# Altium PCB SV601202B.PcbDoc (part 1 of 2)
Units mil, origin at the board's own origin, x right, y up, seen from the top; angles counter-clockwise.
Board outline 3713 x 4037 mil, 6 copper layers (Top Layer, Signal Layer 1, Signal Layer 2, Signal Layer 3, Signal Layer 4, Bottom Layer), stack 60.36 mil thick; 230 components, 115 nets, 621 pads, 197 vias.
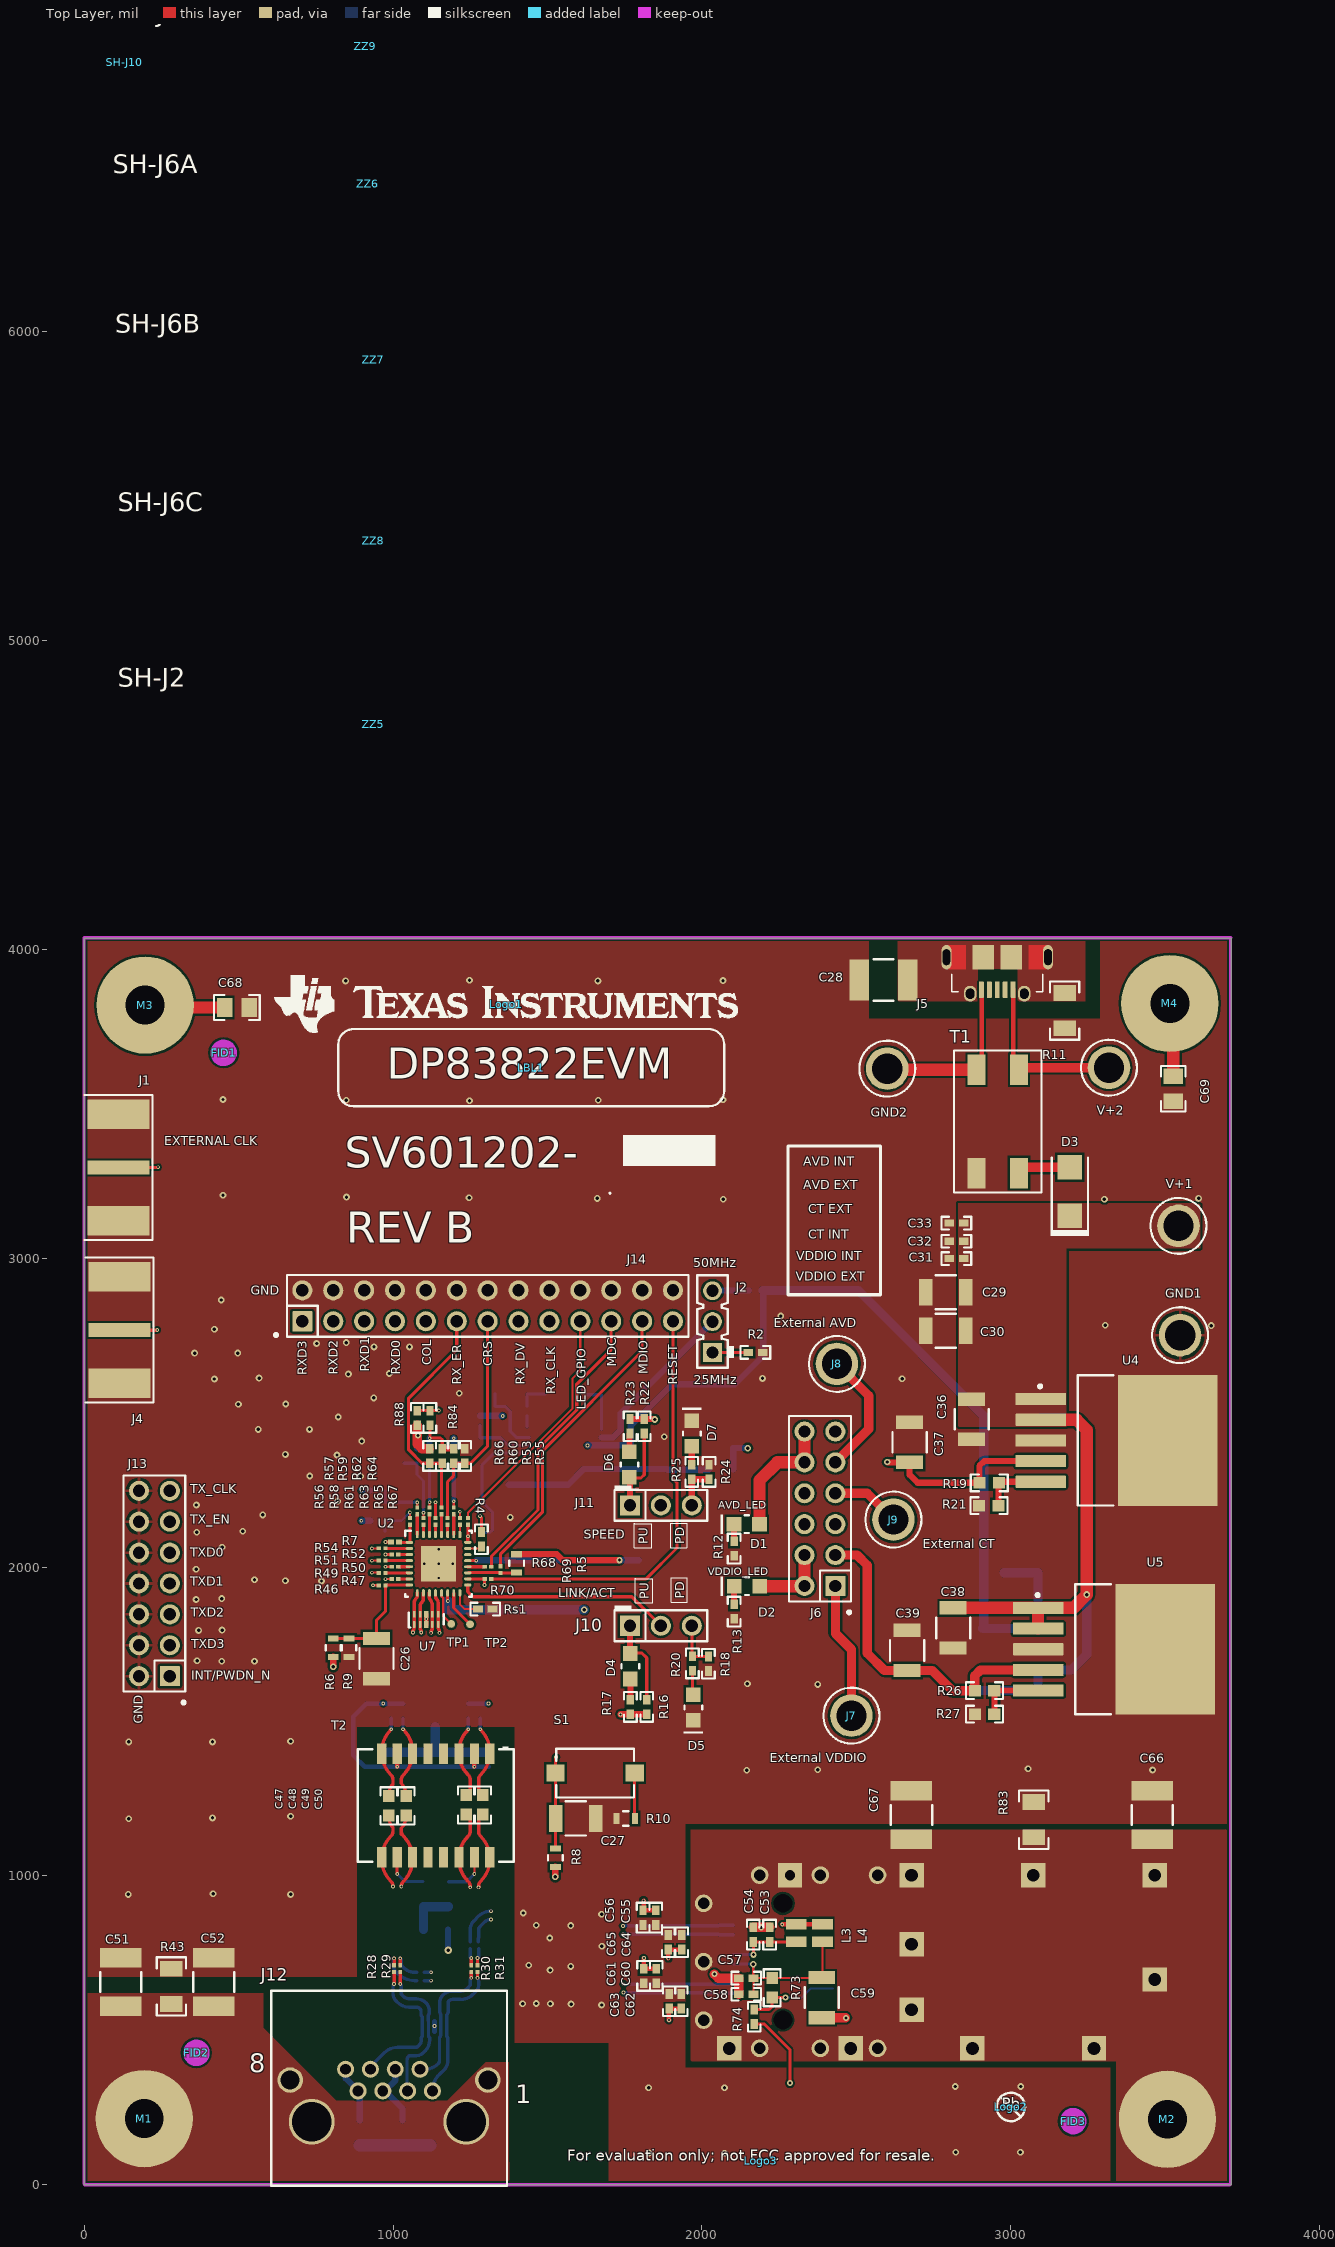
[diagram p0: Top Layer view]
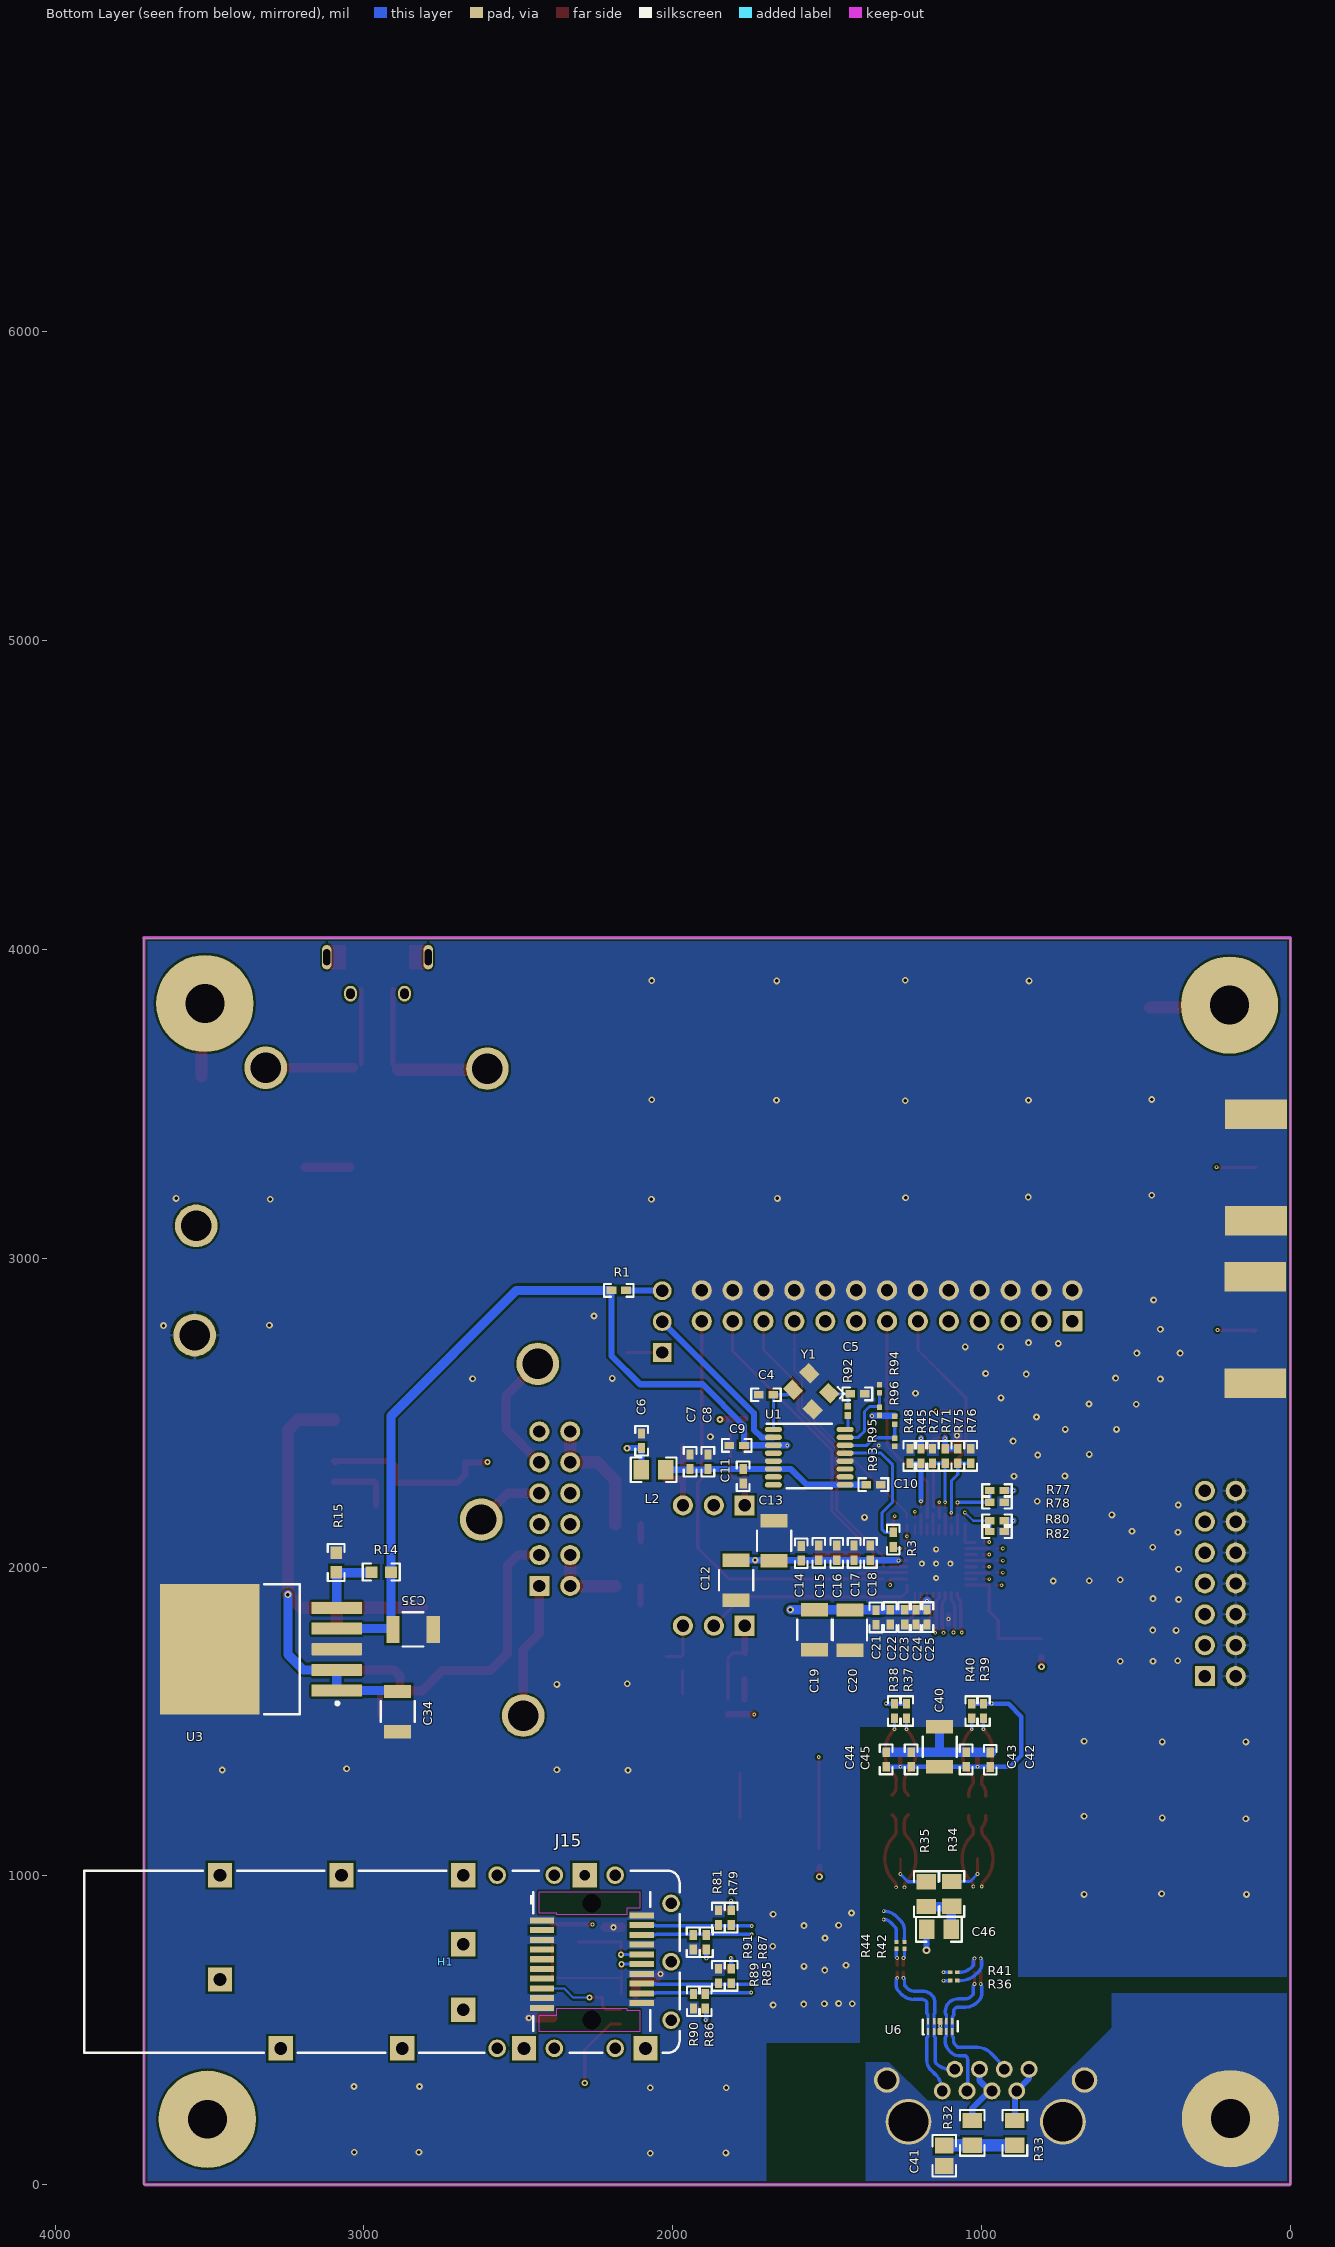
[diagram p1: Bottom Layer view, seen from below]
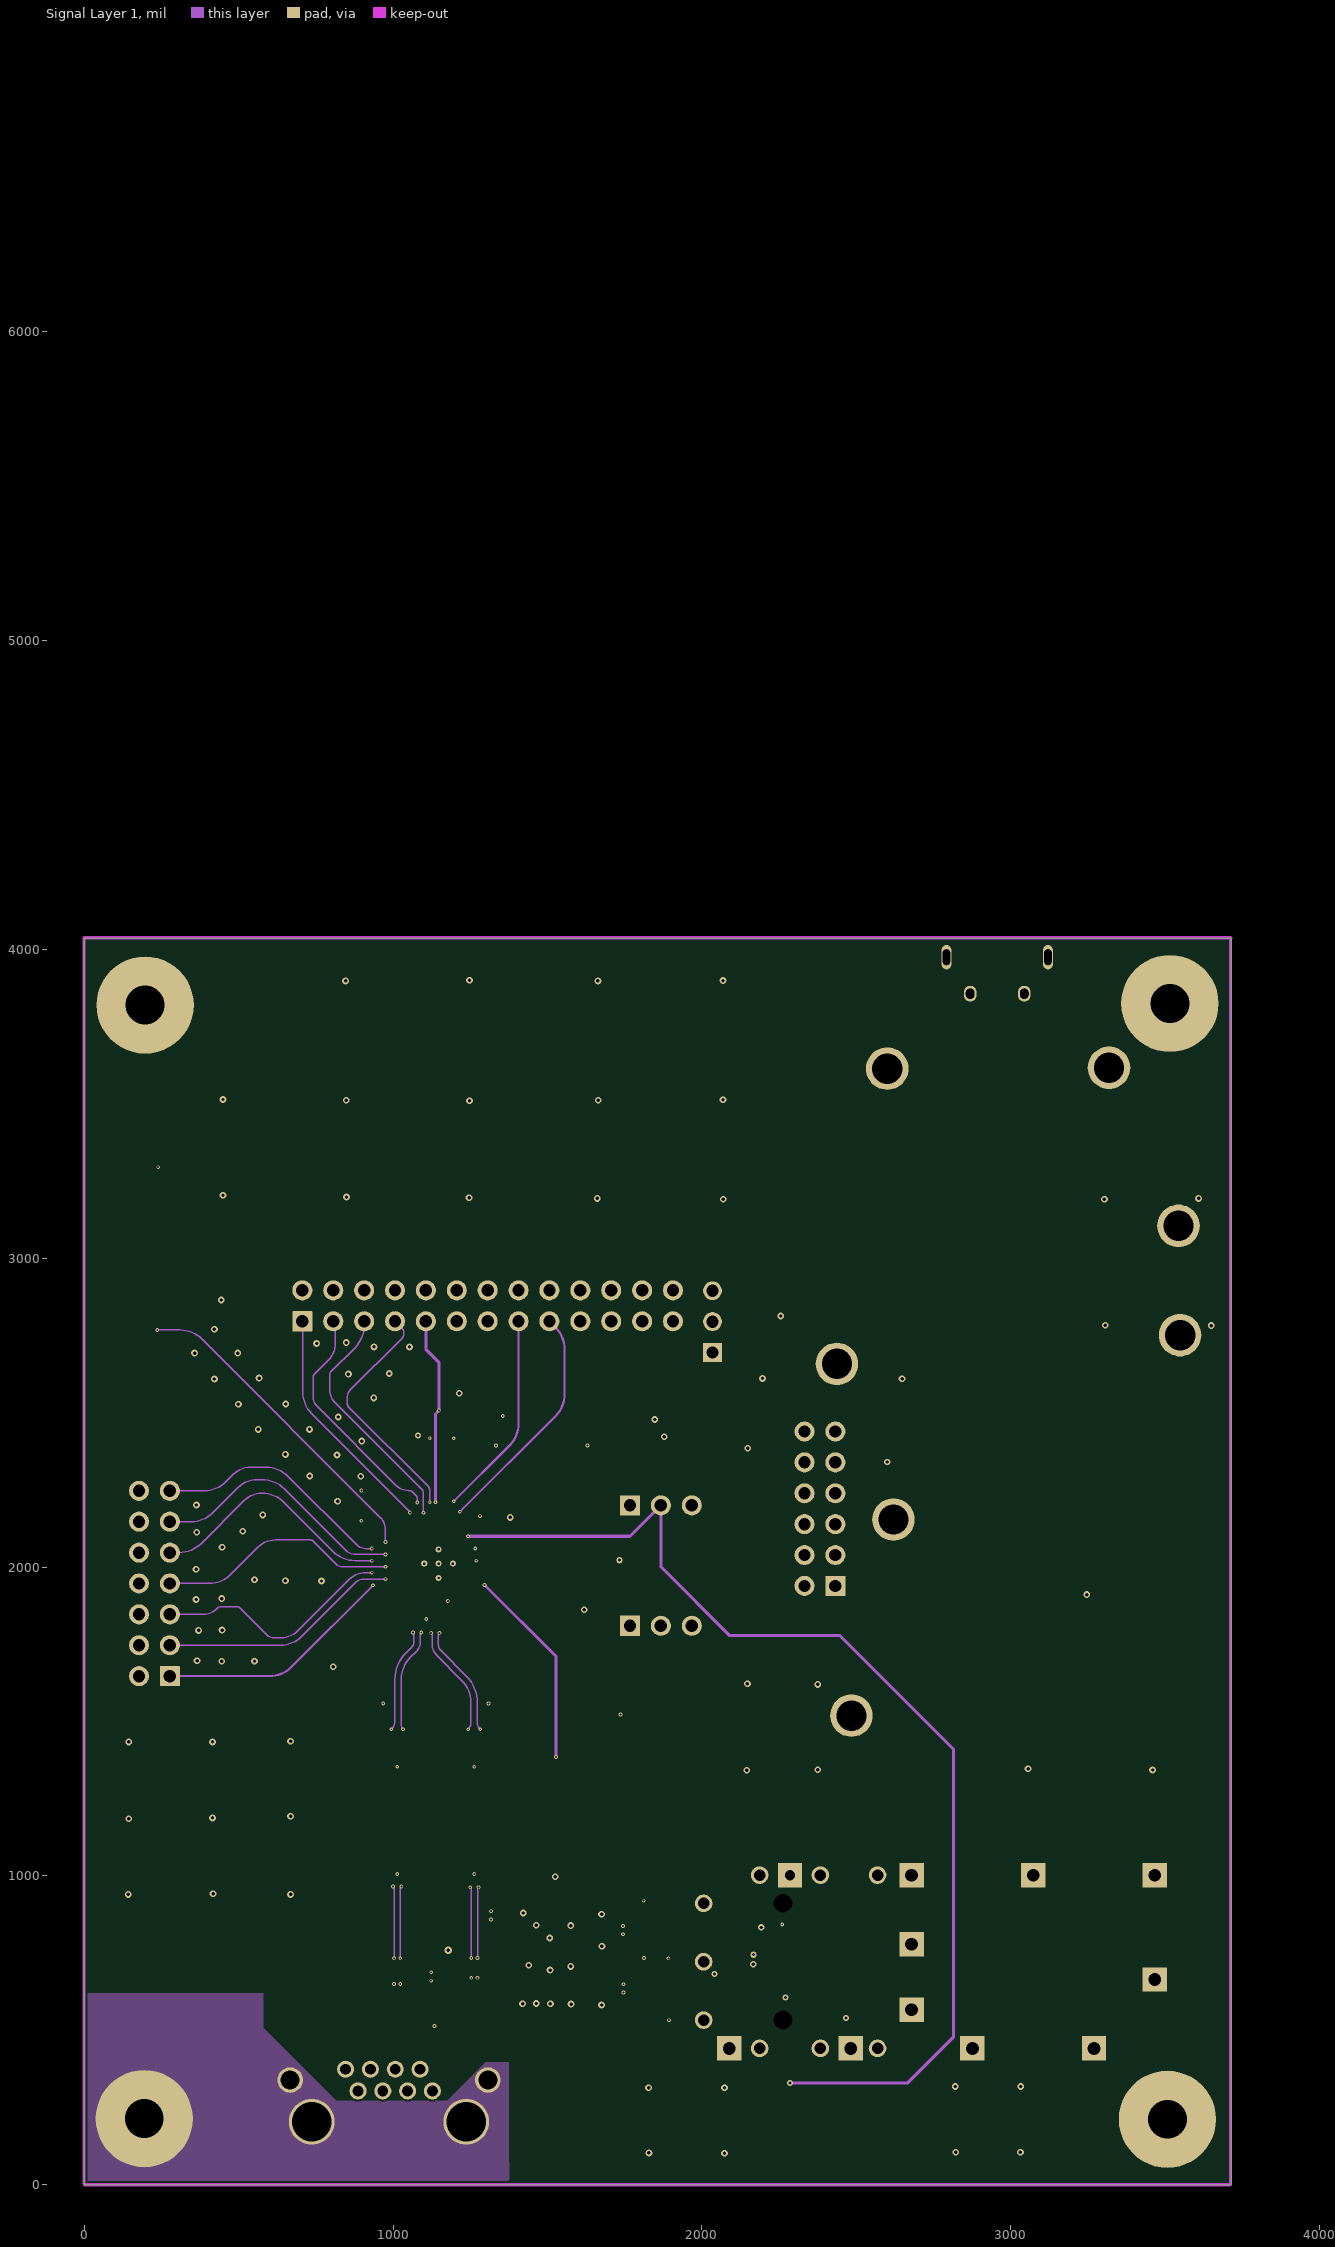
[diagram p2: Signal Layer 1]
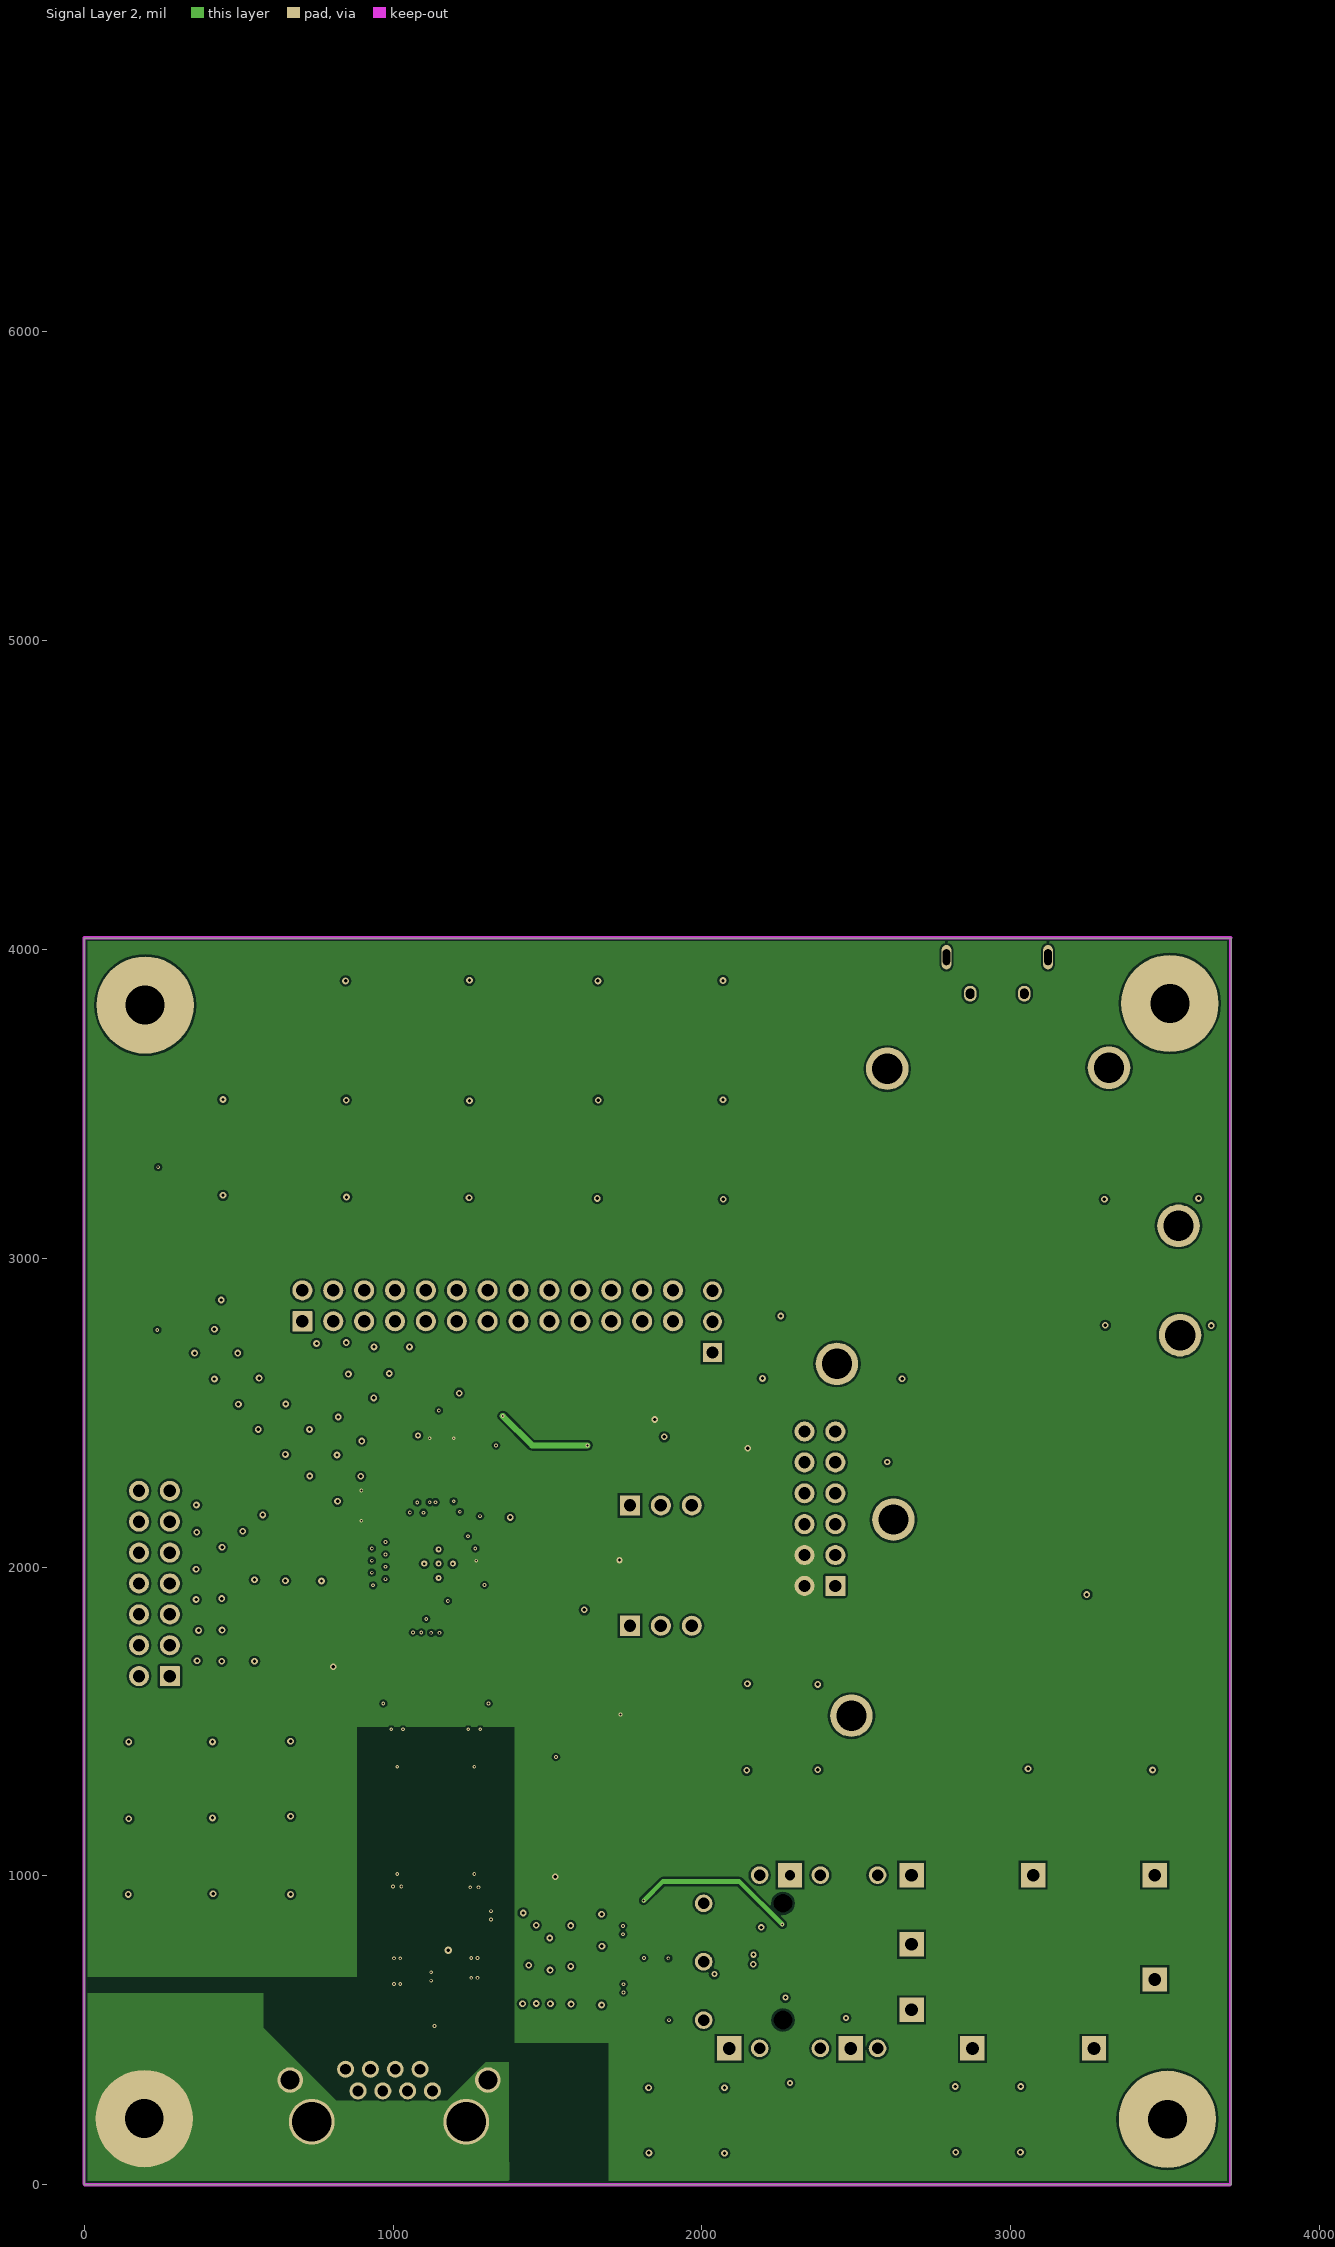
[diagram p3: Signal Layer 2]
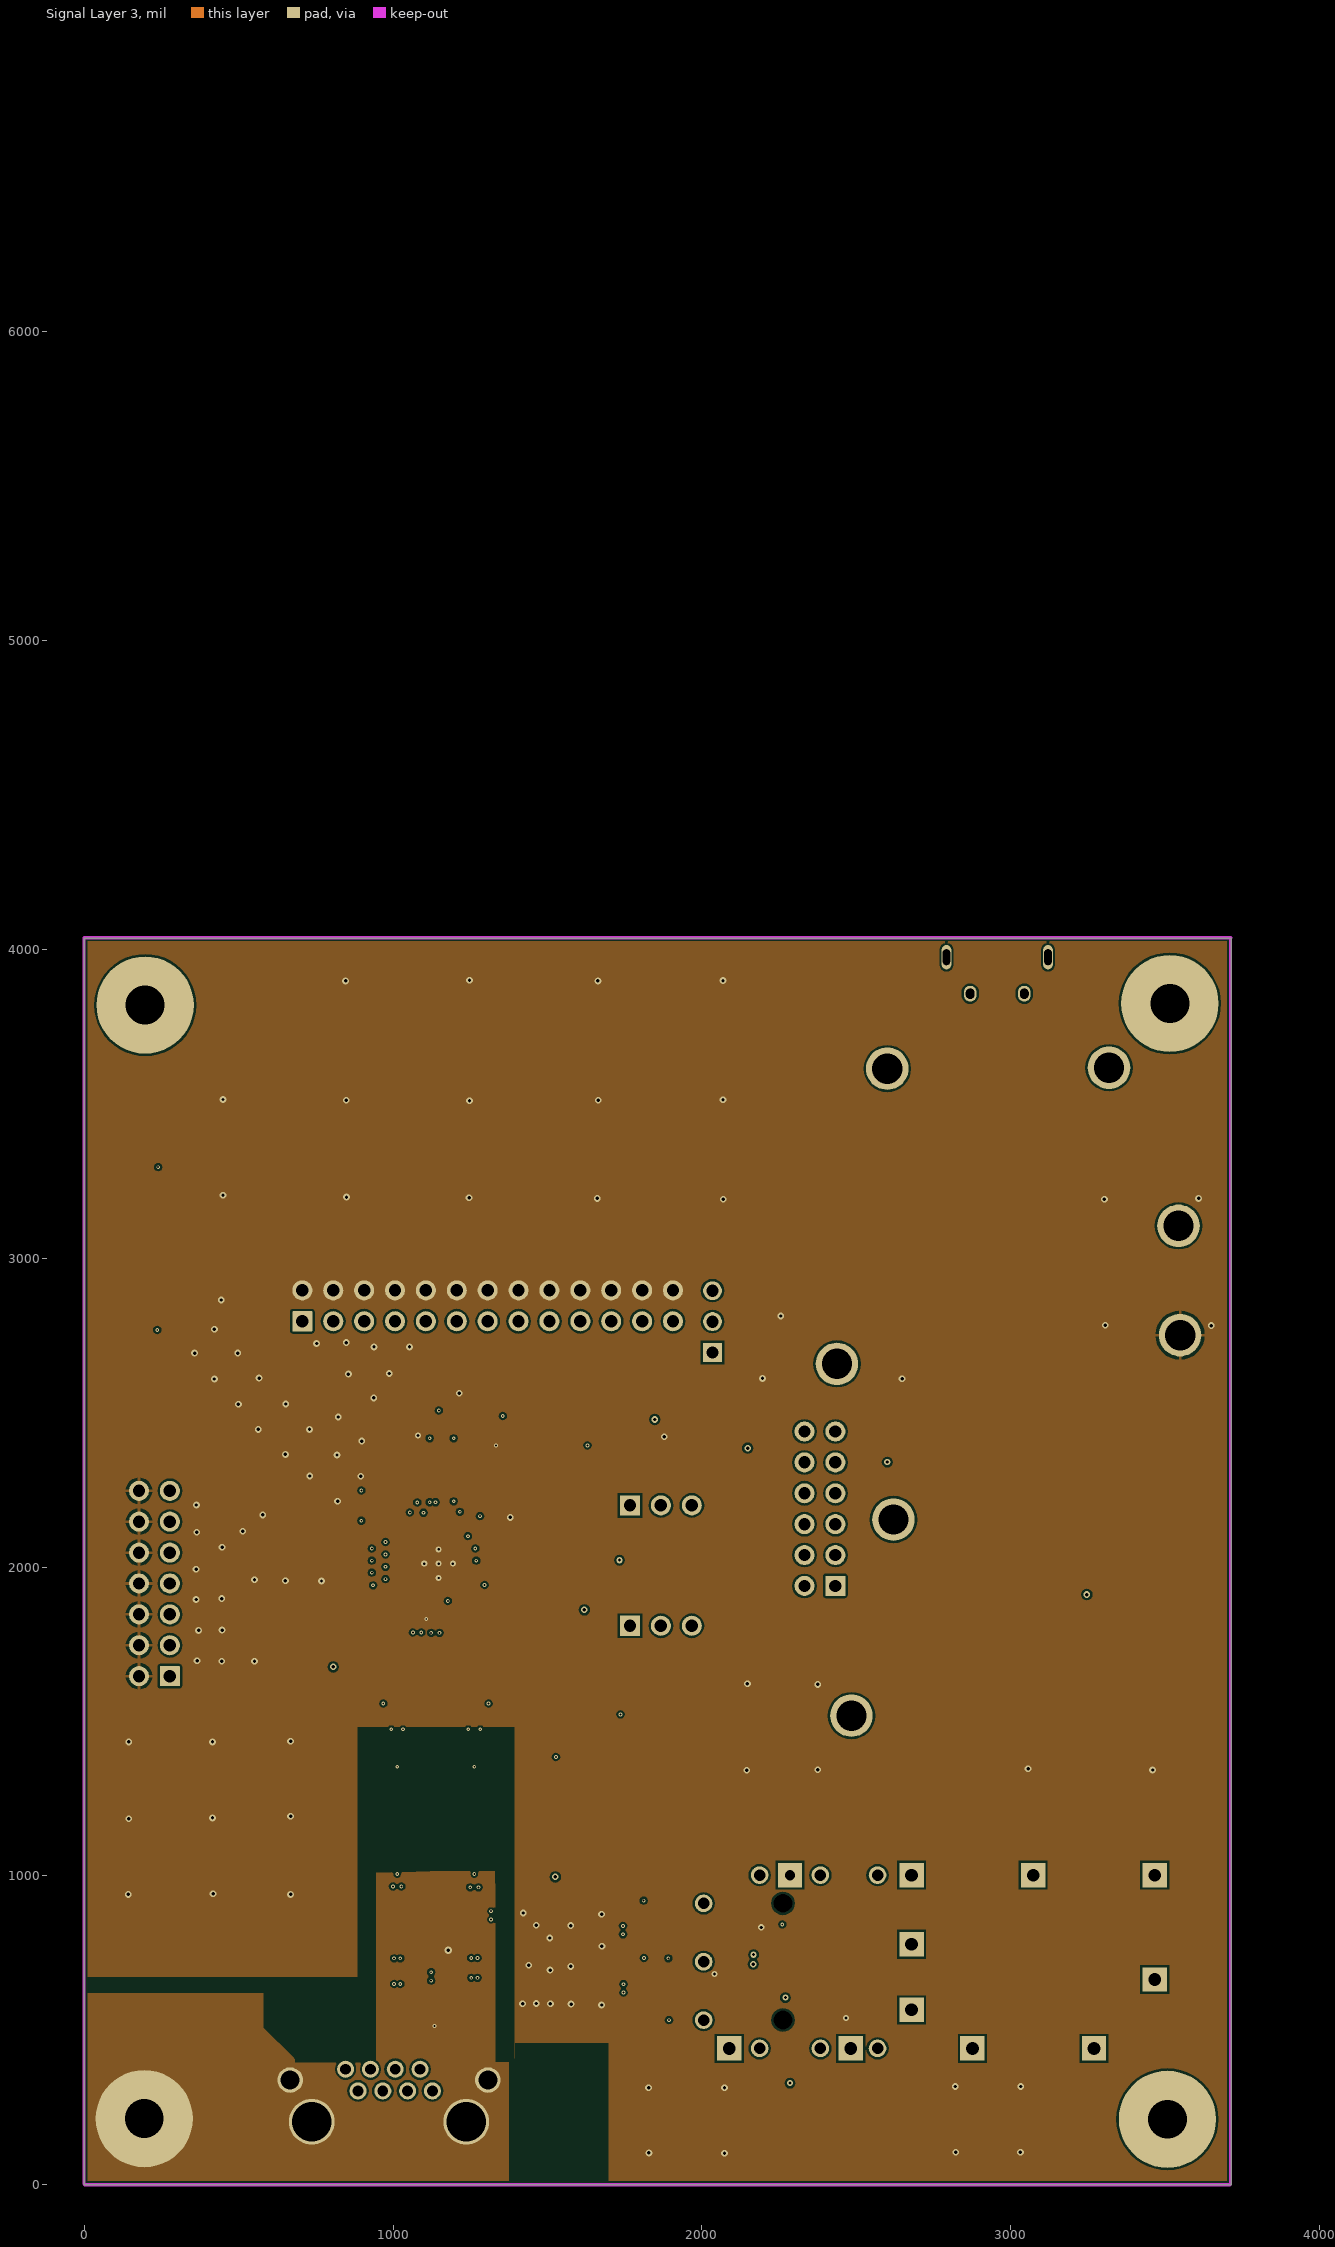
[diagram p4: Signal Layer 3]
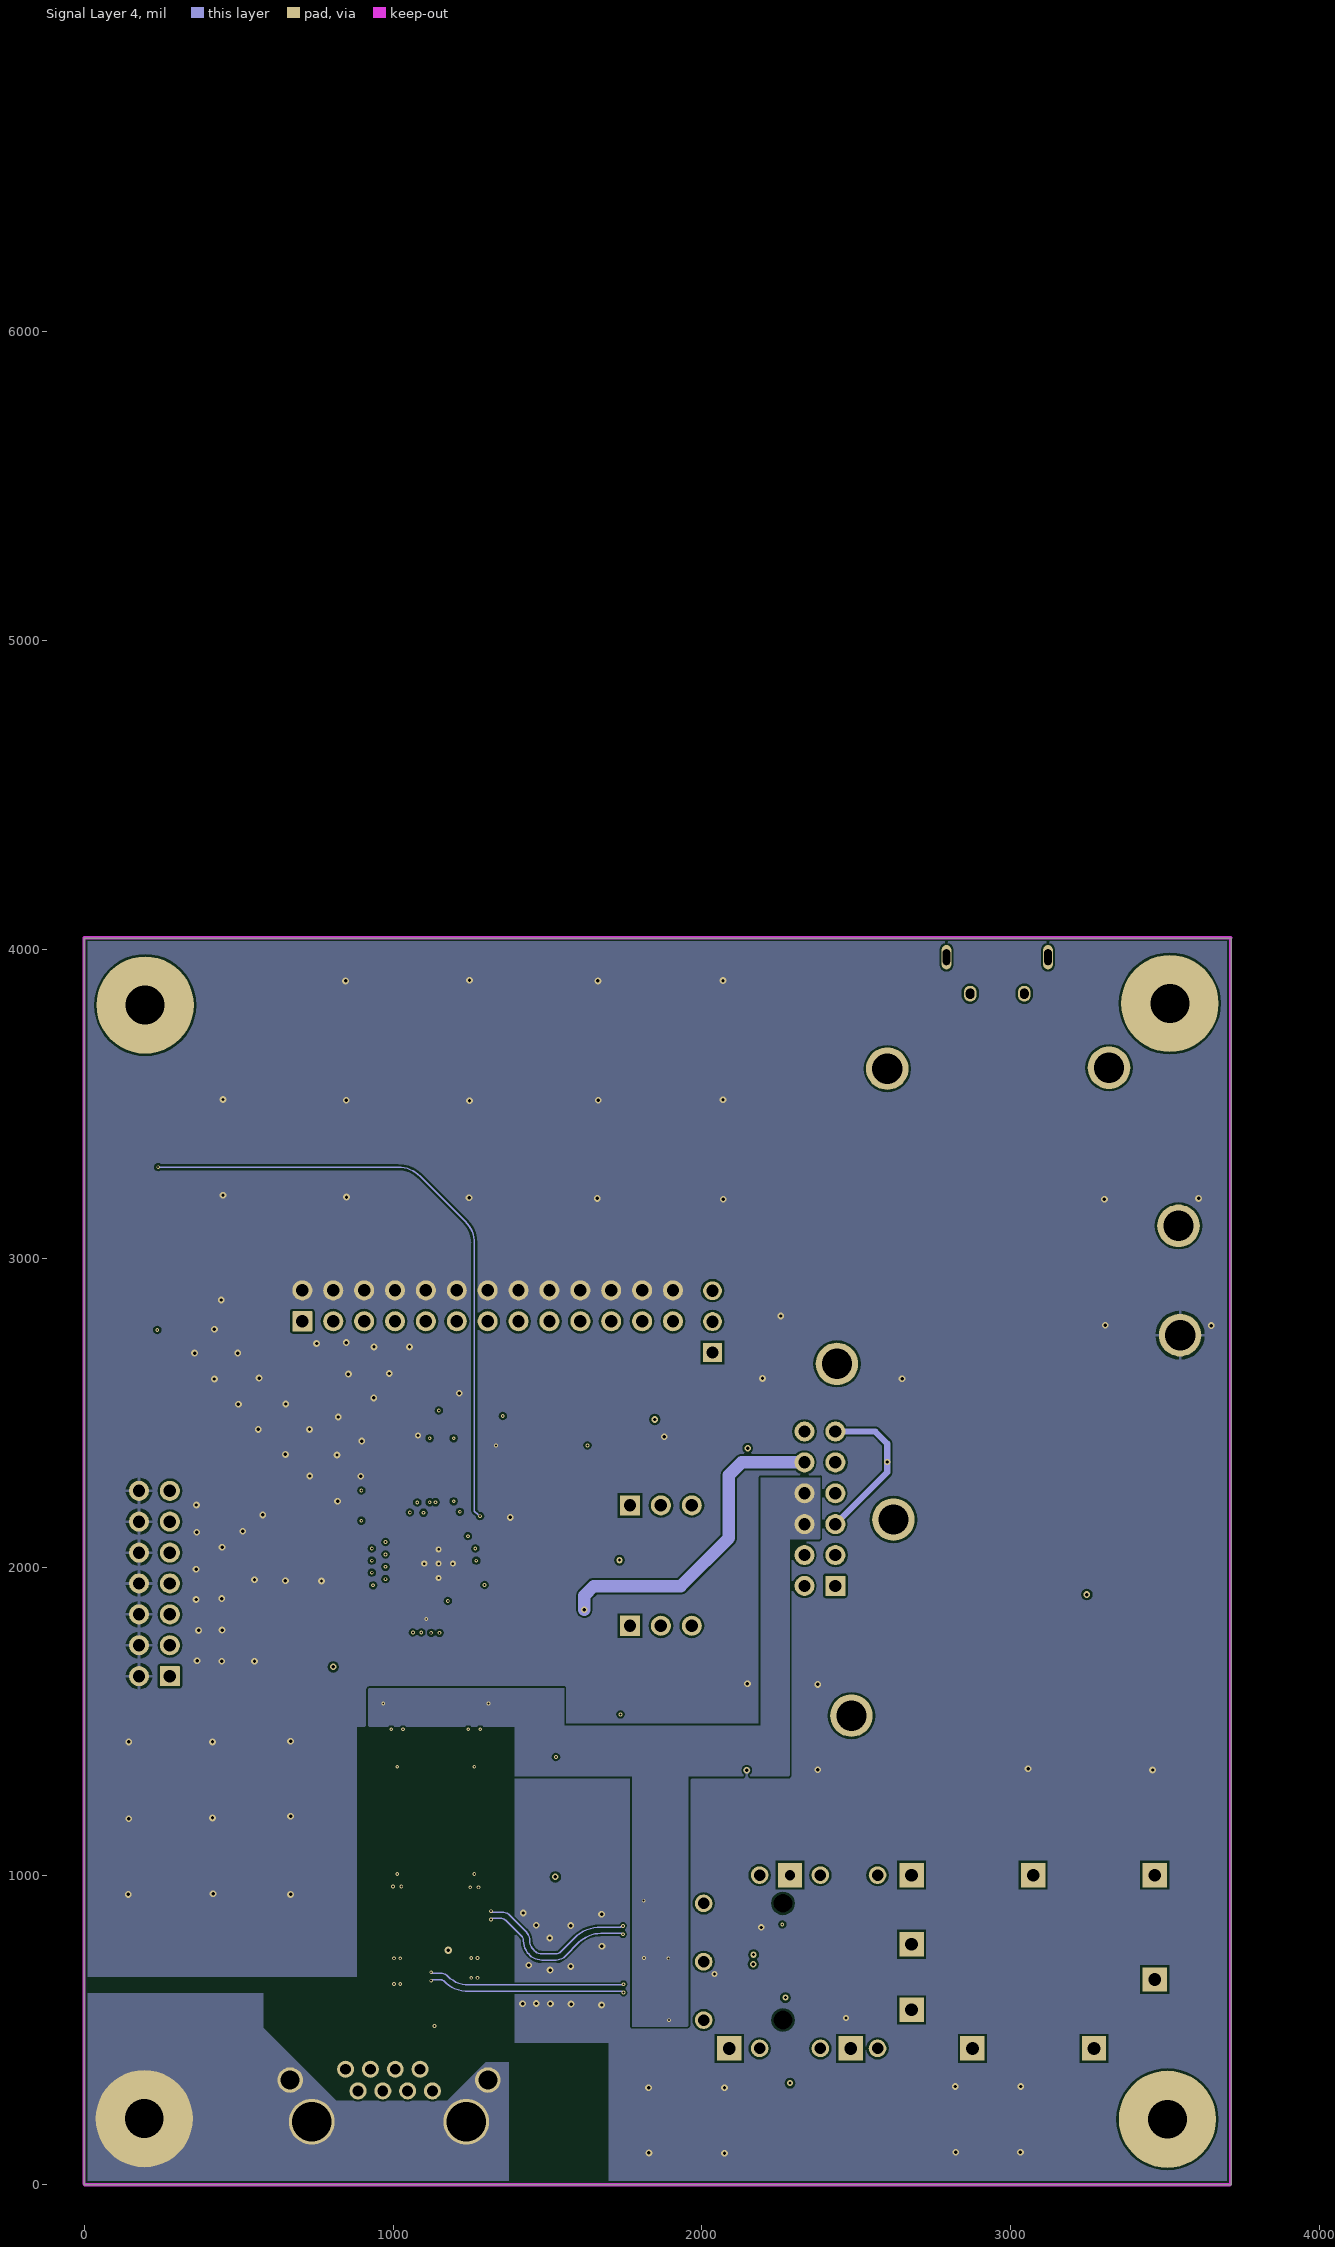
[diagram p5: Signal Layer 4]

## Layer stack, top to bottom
Top Solder: solder mask 0.7, Solder Resist, Dk 3.5
Top Layer: signal copper 1.58
Dielectric1: core 5, FR-4, Dk 4.8
Signal Layer 1: signal copper 1.3
Dielectric 3: prepreg 6, Dk 4.2
Signal Layer 2: signal copper 1.3
Dielectric 2: core 30, Dk 4.2
Signal Layer 3: signal copper 1.3
Dielectric 5: prepreg 6, Dk 4.2
Signal Layer 4: signal copper 1.3
Dielectric 4: core 5, Dk 4.2
Bottom Layer: signal copper 1.58
Bottom Solder: solder mask 0.7, Solder Resist, Dk 3.5

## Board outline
0,0 3713,0 3713,4037 0,4037

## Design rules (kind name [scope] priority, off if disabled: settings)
AssemblyTestPointUsage [All] p1: valid=2
Clearance U1_U6_Clearance [(InComponent('U1') AND InComponent('U6'))] p1: gap=0
Clearance [All] p2: gap=7 except(5: Arc-Arc Arc-THPad Arc-Track Track-Track Track-Via Track-THPad; 5.5: Arc-SMDPad SMDPad-SMDPad Track-SMDPad)
ComponentClearance [All] p1: gap=0 collisioncheckmode=3 verticalgap=0 showdistances=FALSE
DiffPairsRouting [All] p1: maxlimit=16 minlimit=10 mostfreqgap=16 toplayer_mingap=16 toplayer_minwidth=11 toplayer_maxwidth=11 toplayer_prefwidth=11 midlayer1_mingap=16 midlayer1_minwidth=4.5 midlayer1_maxwidth=4.5 midlayer1_prefwidth=4.5 midlayer2_maxgap=10 midlayer2_prefgap=10 midlayer2_minwidth=15 midlayer2_maxwidth=15 midlayer2_prefwidth=15 midlayer3_maxgap=10 midlayer3_prefgap=10 midlayer3_minwidth=15 midlayer3_maxwidth=15 midlayer3_prefwidth=15 midlayer4_mingap=16 midlayer4_minwidth=4.5 midlayer4_maxwidth=4.5 midlayer4_prefwidth=4.5 bottomlayer_mingap=16 bottomlayer_minwidth=11 bottomlayer_maxwidth=11 bottomlayer_prefwidth=11 maxuncoupledlength=2000
FabricationTestPointUsage [All] p1: valid=2 allowmultiple=FALSE
HoleSize [All] p1: absolutevalues=TRUE maxlimit=180 minlimit=1 maxpercent=80.000 minpercent=20.000
MinimumSolderMaskSliver [All] p1: minsoldermaskwidth=3.5
PlaneConnect [All] p1: planeconnectstyle=Direct reliefexpansion=20 reliefentries=4 reliefconductorwidth=10 reliefairgap=10
PolygonConnect GND1-1 [InComponent('GND1')] p1: connectstyle=Relief reliefconductorwidth=10 reliefentries=4 polygonreliefangle="90 Angle" airgapwidth=10
PolygonConnect "J11 Strain relief" [InComponent('J11')] p2: connectstyle=Relief reliefconductorwidth=10 reliefentries=4 polygonreliefangle="90 Angle" airgapwidth=10
PolygonConnect "J13 strain relief" [InComponent('J13')] p3: connectstyle=Relief reliefconductorwidth=10 reliefentries=4 polygonreliefangle="90 Angle" airgapwidth=10
PolygonConnect [All] p4: connectstyle=Direct reliefconductorwidth=10 reliefentries=4 polygonreliefangle="90 Angle" airgapwidth=10
RoutingVias [All] p1: holewidth=12 width=23 viastyle="Through Hole" minholewidth=6 minwidth=12 maxholewidth=40 maxwidth=65
SilkToSilkClearance [All] p1: silktosilkclearance=0
SilkToSolderMaskClearance [IsPad] p1: minsilkscreentomaskgap=0 clearancetoexposedcopper=TRUE
SolderMaskExpansion [All] p1: expansion=0
UnpouredPolygon [All] p1: allowunpoured=FALSE
Width [All] p1: maxlimit=100 minlimit=4 preferedwidth=5.4
20 further rules are at their usual default settings.

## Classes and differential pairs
component class Power: C28 C29 C30 C31 C32 C33 C34 C35 C36 C37 C38 C39 D1 D2 D3 D4 D5 D6 D7 GND1 GND2 J5 J6 J7 J8 J9 J10 J11 R11 R12 R13 R14 R15 R16 R17 R18 R19 R20 R21 R22 R23 R24 R25 R26 R27 SH-J6A SH-J6B SH-J6C SH-J10 T1 U3 U4 U5 V+1 V+2 ZZ6 ZZ7 ZZ8 ZZ9
component class MAIN: C4 C5 C6 C7 C8 C9 C10 C11 C12 C13 C14 C15 C16 C17 C18 C19 C20 C21 C22 C23 C24 C25 C26 C27 J1 J2 J4 L2 R1 R2 R3 R4 R5 R6 R7 R8 R9 R10 R92 R93 R94 R95 R96 Rs1 S1 SH-J2 TP1 TP2 U1 U2 Y1 ZZ5
component class Header: J2 J6 J10 J11 J13 J14
component class Connectors: C53 C54 C55 C56 C57 C58 C59 C60 C61 C62 C63 C64 C65 C66 C67 J13 J14 J15 L3 L4 R45 R46 R47 R48 R49 R50 R51 R52 R53 R54 R55 R56 R57 R58 R59 R60 R61 R62 R63 R64 R65 R66 R67 R68 R69 R70 R71 R72 R73 R74 R75 R76 R77 R78 R79 R80 R81 R82 R83 R84 R85 R86 R87 R88 R89 R90 R91
component class AFE: C40 C41 C42 C43 C44 C45 C46 C47 C48 C49 C50 C51 C52 J12 R28 R29 R30 R31 R32 R33 R34 R35 R36 R37 R38 R39 R40 R41 R42 R43 R44 T2 U6 U7
component class Logo: Logo1
component class SV601202B_Hardware: C68 C69 FID1 FID2 FID3 H1 LBL1 Logo1 Logo2 Logo3 M1 M2 M3 M4 ZZ1 ZZ2 ZZ3 ZZ4
component class FiducialMark: FID1 FID2 FID3
component class AssemblyNote: ZZ1 ZZ2 ZZ3 ZZ4
component class Label: LBL1
component class Shunt: SH-J2 SH-J6A SH-J6B SH-J6C SH-J10
differential pair TXD_MAG: +TXD_MAG_P -TXD_MAG_N
differential pair TXD_CABLE: +TXD_CABLE_P -TXD_CABLE_N
differential pair RXD_MAG: +RXD_MAG_P -RXD_MAG_N
differential pair RXD_CABLE: +RXD_CABLE_P -RXD_CABLE_N
differential pair FX_TD: +FX_TD_P -FX_TD_N
differential pair FX_RD: +FX_RD_P -FX_RD_N
differential pair RXD: +RXD_P -RXD_N
differential pair TXD: +TXD_P -TXD_N

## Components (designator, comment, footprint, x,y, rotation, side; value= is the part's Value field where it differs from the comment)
C4 "C0402C120J3GACAUTO" 0402 1698,2558 r0 bottom
C5 "C0402C120J3GACAUTO" 0402 1402,2561 r180 bottom
C6 "GRM155R61C225KE11D" 0402 2101,2409 r90 bottom
C7 "GRM155R61C225KE11D" 0402 1944,2341 r90 bottom
C8 "GRM155R71C104KA88D" 0402 1886,2341 r90 bottom
C9 "CGA2B3X7R1H103K050BB" 0402 1793,2394 r0 bottom
C10 "CGA2B3X7R1H103K050BB" 0402 1350,2267 r180 bottom
C11 "CGA2B3X7R1H103K050BB" 0402 1772,2294 r270 bottom
C12 "CGA6P1X7R1C226M250AC" 1210_280 1795,1957 r270 bottom
C13 "CGA6P1X7R1E106M250AC" 1210_280 1672,2085 r90 bottom
C14 "C1005X7S1A105K050BC" 0402 1584,2045 r90 bottom
C15 "GRM155R71C104KA88D" 0402 1527,2046 r90 bottom
C16 "CGA2B3X7R1H103K050BB" 0402 1469,2046 r90 bottom
C17 "CGA2B2C0G1H102J050BA" 0402 1413,2046 r90 bottom
C18 "CGA2B2C0G1H101J050BA" 0402 1360,2046 r90 bottom
C19 "CGA6P1X7R1C226M250AC" 1210_280 1541,1797 r270 bottom
C20 "CGA6P1X7R1E106M250AC" 1210_280 1426,1796 r270 bottom
C21 "C1005X7S1A105K050BC" 0402 1342,1837 r270 bottom
C22 "GRM155R71C104KA88D" 0402 1296,1838 r270 bottom
C23 "CGA2B3X7R1H103K050BB" 0402 1249,1838 r270 bottom
C24 "CGA2B2C0G1H102J050BA" 0402 1212,1838 r270 bottom
C25 "CGA2B2C0G1H101J050BA" 0402 1177,1838 r270 bottom
C26 "CGA6P1X7R1E106M250AC" 1210_280 946,1704 r270 top
C27 "CGA6P1X7R1E106M250AC" 1210_280 1591,1186 r0 top
C28 "1812GC472KAT1A" 1812_254 2588,3901 r0 top
C29 "CGA6P1X7R1C226M250AC" 1210_280 2789,2890 r180 top
C30 "CGA6P1X7R1E106M250AC" 1210_280 2789,2765 r180 top
C31 "CGA2B3X7R1H103K050BB" 0402 2824,2999 r180 top
C32 "CGA2B2C0G1H102J050BA" 0402 2824,3055 r180 top
C33 "CGA2B2C0G1H101J050BA" 0402 2824,3114 r180 top
C34 "CGA6P1X7R1E106M250AC" 1210_280 2891,1532 r270 bottom
C35 "CGA6P1X7R1E106M250AC" 1210_280 2841,1798 r180 bottom
C36 "CGA6P1X7R1E106M250AC" 1210_280 2873,2479 r270 top
C37 "CGA6P1X7R1C226M250AC" 1210_280 2672,2404 r90 top
C38 "CGA6P1X7R1E106M250AC" 1210_280 2813,1803 r270 top
C39 "CGA6P1X7R1C226M250AC" 1210_280 2664,1730 r90 top
C40 "CGA6P1X7R1C226M250AC" 1210_280 1136,1418 r90 bottom
C41 "CGA4J3C0G2E103J125AA" 0805 1121,94 r270 bottom
C42 "C1005X7S1A105K050BC" 0402 972,1376 r90 bottom
C43 "GRM155R71C104KA88D" 0402 1050,1377 r90 bottom
C44 "C1005X7S1A105K050BC" 0402 1309,1377 r90 bottom
C45 "GRM155R71C104KA88D" 0402 1228,1377 r90 bottom
C46 "CGA4J3C0G2E103J125AA" 0805_HV 1138,827 r0 bottom
C47 "CGA3E2X8R1E104K080AA" 0603 986,1227 r90 top
C48 "CGA3E2X8R1E104K080AA" 0603 1042,1227 r90 top
C49 "CGA3E2X8R1E104K080AA" 0603 1237,1230 r90 top
C50 "CGA3E2X8R1E104K080AA" 0603 1290,1230 r90 top
C51 "1812GC472KAT1A" 1812_254 118,657 r270 top
C52 "1812GC472KAT1A" 1812_254 419,657 r270 top
C53 "CGA2B3X7R1H103K050BB" 0402 2219,810 r90 top
C54 "GRM155R71C104KA88D" 0402 2166,810 r90 top
C55 "C1005X7S1A105K050BC" 0402 1850,865 r270 top
C56 "GRM155R71C104KA88D" 0402 1809,865 r270 top
C57 "CGA2B3X7R1H103K050BB" 0402 2143,669 r180 top
C58 "GRM155R71C104KA88D" 0402 2143,617 r180 top
C59 "CGA6P1X7R1E106M250AC" 1210_280 2388,606 r270 top
C60 "C1005X7S1A105K050BC" 0402 1852,676 r270 top
C61 "GRM155R71C104KA88D" 0402 1811,676 r270 top
C62 "C1005X7S1A105K050BC" 0402 1933,594 r90 top
C63 "GRM155R71C104KA88D" 0402 1894,594 r90 top
C64 "C1005X7S1A105K050BC" 0402 1934,785 r90 top
C65 "GRM155R71C104KA88D" 0402 1891,785 r90 top
C66 "1812GC472KAT1A" 1812_254 3458,1197 r270 top
C67 "1812GC472KAT1A" 1812_254 2678,1197 r270 top
C68 "08051C472KAT2A" 0805_HV 494,3812 r0 top
C69 "08051C472KAT2A" 0805_HV 3526,3549 r270 top
D1 "QTLP630C4TR" QTLP630C_Green 2145,2139 r180 top
D2 "QTLP630C4TR" QTLP630C_Green 2145.31,1938.15 r180 top
D3 "NRVBA160T3G" SMA 3191,3216 r90 top
D4 "QTLP630C4TR" QTLP630C_Green 1768,1679 r90 top
D5 "QTLP630C4TR" QTLP630C_Green 1972,1545 r270 top
D6 "QTLP630C4TR" QTLP630C_Green 1765,2332 r270 top
D7 "QTLP630C4TR" QTLP630C_Green 1967,2432 r90 top
FID1 "Fiducial" Fiducial10-20 451,3665 r0 top
FID2 "Fiducial" Fiducial10-20 363,427 r0 top
FID3 "Fiducial" Fiducial10-20 3202,206 r0 top
GND1 "Suggest using a net name here" Keystone1502-2 3548,2751 r90 top
GND2 "Suggest using a net name here" Keystone1502-2 2600,3614 r180 top
H1 "U77-A1118-200T" Amphenol_U77-A1118-200T 2285,722 r180 bottom
J1 "EXTERNAL CLK" Emerson_142-0701-851 1,3294 r90 top
J2 "TSW-103-07-T-S" Samtec_TSW-103-07-T-S 2034,2795 r90 top
J4 "RXD3" Emerson_142-0701-851 4,2768 r90 top
J5 "0475890001" Molex_0475890001 2956,4032 r180 top
J6 "TSW-106-07-G-D" TSW-106-07-G-D 2382,2189 r90 top
J7 "External VDDIO" Keystone1502-2 2484,1519 r270 top
J8 "External AVD" Keystone1502-2 2437,2658 r270 top
J9 "External CT" Keystone1502-2 2620,2154 r270 top
J10 "TSW-103-07-G-S" TSW-103-07-G-S 1867,1810 r0 top
J11 "TSW-103-07-G-S" TSW-103-07-G-S 1867,2200 r0 top
J12 "1-406541-1" TEC_1-406541-1 987,311 r0 top
J13 "TSW-107-07-G-D" TSW-107-07-G-D 227,1947 r90 top
J14 "TSW-113-07-G-D" TSW-113-07-G-D 1306,2846 r0 top
J15 "1367073-1" TE_1367073-1 2261.99,722.28 r180 bottom
L2 "BLM21BD121SN1D" 0805_HV 2062,2315 r180 bottom
L3 "IFSC0806AZER1R0M01" IFSC-0806AZ-01 2305,815 r270 top
L4 "IFSC0806AZER1R0M01" IFSC-0806AZ-01 2390,815 r270 top
LBL1 "Size: 1.25\" x 0.25\"" Label_1250x250 1447,3617 r0 top
Logo1 "Texas Instruments" TI_Horizontal_Overlay_Medium 1366,3823 r0 top
Logo2 "Pb-Free Symbol" Pb-Free_Overlay_Small 3000,252 r0 top
Logo3 "FCC disclaimer" FCC_disclaimer 2190,78 r0 top
M1 "TESTPOINT" TESTPOINT 194,214 r0 top
M2 "TESTPOINT" TESTPOINT 3507,212 r0 top
M3 "TESTPOINT" TESTPOINT 197,3820 r0 top
M4 "TESTPOINT" TESTPOINT 3515,3825 r0 top
R1 "CRCW04021K00FKED" 0402 2175,2896 r0 bottom
R2 "CRCW04021K00FKED" 0402 2173,2695 r180 top
R3 "CRCW040218R0JNED" 0402 1286,2089 r270 bottom
R4 "CRCW04020000Z0ED" 0402 1286,2090 r270 top
R5 "TNPW06032K21BEEA" TNPW0603 1400,2012 r90 top
R6 "TNPW06032K21BEEA" TNPW0603 806,1739 r270 top
R7 "ERJ-1GE0R00C" 0201 1006,2081 r0 top
R8 "TNPW06032K21BEEA" TNPW0603 1525,1059 r270 top
R9 "TNPW06032K21BEEA" TNPW0603 857,1739 r90 top
R10 "TNPW06032K21BEEA" TNPW0603 1753,1186 r0 top
R11 "CRCW12061M00FKEA" 1206 3174,3802 r270 top
R12 "CRCW0402470RJNED" 0402 2104,2060 r90 top
R13 "CRCW0402470RJNED" 0402 2104,1856 r90 top
R14 "RT0603BRD071K2L" 0603 2944,1984 r180 bottom
R15 "ERA-3AEB242V" 0603 3090,2015 r270 bottom
R16 "CRCW04022K49FKED" 0402 1821,1547 r90 top
R17 "CRCW0402470RJNED" 0402 1768,1547 r270 top
R18 "CRCW04022K49FKED" 0402 2021,1687 r90 top
R19 "CRCW06034K22FKEA" 0603 2930,2273 r180 top
R20 "CRCW0402470RJNED" 0402 1969,1688 r270 top
R21 "ERA-3AEB242V" 0603 2929,2199 r0 top
R22 "CRCW04022K49FKED" 0402 1813,2456 r270 top
R23 "CRCW0402470RJNED" 0402 1767,2456 r90 top
R24 "CRCW04022K49FKED" 0402 2023,2308 r270 top
R25 "CRCW0402470RJNED" 0402 1967,2308 r90 top
R26 "CRCW06034K22FKEA" 0603 2915,1600 r180 top
R27 "ERA-3AEB242V" 0603 2915,1524 r0 top
R28 "ERJ-1GE0R00C" 0201L 1003,700 r270 top
R29 "ERJ-1GE0R00C" 0201L 1023,700 r270 top
R30 "ERJ-1GE0R00C" 0201L 1253,700 r270 top
R31 "ERJ-1GE0R00C" 0201L 1273,700 r270 top
R32 "CRCW080575R0JNEA" 0805_HV 1030,168 r90 bottom
R33 "CRCW080575R0JNEA" 0805_HV 892,168 r90 bottom
R34 "CRCW080575R0JNEA" 0805_HV 1096,942 r90 bottom
R35 "CRCW080575R0JNEA" 0805_HV 1179,941 r90 bottom
R36 "ERJ-1GE0R00C" 0201L 1090,661 r0 bottom
R37 "CRCW040249R9FKED" 0402 1243,1534 r90 bottom
R38 "CRCW040249R9FKED" 0402 1282,1534 r90 bottom
R39 "CRCW040249R9FKED" 0402 994,1534 r90 bottom
R40 "CRCW040249R9FKED" 0402 1032,1534 r90 bottom
R41 "ERJ-1GE0R00C" 0201L 1090,688 r0 bottom
R42 "ERJ-1GE0R00C" 0201L 1250,775 r90 bottom
R43 "CRCW12061M00FKEA" 1206 282,642 r90 top
R44 "ERJ-1GE0R00C" 0201L 1276,775 r90 bottom
R45 "CRCW040210K0FKED" 0402 1196,2360 r90 bottom
R46 "ERJ-1GE0R00C" 0201L 964,1941 r0 top
R47 "ERJ-1GE0R00C" 0201L 1006,1962 r0 top
R48 "CRCW04022K49FKED" 0402 1232,2360 r270 bottom
R49 "ERJ-1GE0R00C" 0201L 964,1981 r0 top
R50 "ERJ-1GE0R00C" 0201L 1006,2001 r0 top
R51 "ERJ-1GE0R00C" 0201L 964,2021 r0 top
R52 "ERJ-1GE0R00C" 0201L 1006,2041 r0 top
R53 "CRCW040213K0FKED" 0402 1196,2360 r90 top
R54 "ERJ-1GE0R00C" 0201L 964,2061 r0 top
R55 "CRCW04021K96FKED" 0402 1232,2360 r270 top
R56 "ERJ-1GE0R00C" 0201L 1054,2148 r270 top
R57 "ERJ-1GE0R00C" 0201L 1078,2182 r270 top
R58 "ERJ-1GE0R00C" 0201L 1098,2148 r270 top
R59 "ERJ-1GE0R00C" 0201L 1118,2182 r270 top
R60 "CRCW040213K0FKED" 0402 1159,2360 r90 top
R61 "ERJ-1GE0R00C" 0201L 1137,2148 r270 top
R62 "ERJ-1GE0R00C" 0201L 1156,2182 r270 top
R63 "ERJ-1GE0R00C" 0201L 1176,2148 r270 top
R64 "ERJ-1GE0R00C" 0201L 1196,2182 r270 top
R65 "ERJ-1GE0R00C" 0201L 1216,2148 r270 top
R66 "CRCW04021K96FKED" 0402 1118,2360 r270 top
R67 "ERJ-1GE0R00C" 0201L 1242,2148 r270 top
R68 "ERJ-1GE0R00C" 0201L 1307,2001 r180 top
R69 "ERJ-1GE0R00C" 0201L 1348,1992 r270 top
R70 "ERJ-1GE0R00C" 0201L 1307,1962 r180 top
R71 "CRCW040210K0FKED" 0402 1118,2360 r90 bottom
R72 "CRCW04022K49FKED" 0402 1159,2360 r270 bottom
R73 "RC0603JR-0710KL" 0603 2227,638 r90 top
R74 "RC0402JR-070RL" 0402 2169,544 r90 top
R75 "CRCW040210K0FKED" 0402 1077,2360 r90 bottom
R76 "CRCW04022K49FKED" 0402 1035,2360 r270 bottom
R77 "CRCW040210K0FKED" 0402 950,2248 r180 bottom
R78 "CRCW04022K49FKED" 0402 950,2210 r0 bottom
R79 "CRCW040282R0JNED" 0402 1811,865 r90 bottom
R80 "CRCW040210K0FKED" 0402 950,2150 r180 bottom
R81 "CRCW0402130RJNED" 0402 1852,865 r270 bottom
R82 "CRCW04022K49FKED" 0402 950,2115 r0 bottom
R83 "CRCW12061M00FKEA" 1206 3074,1182 r90 top
R84 "CRCW04026K20JNED" 0402 1119,2483 r270 top
R85 "CRCW040282R0JNED" 0402 1811,676 r90 bottom
R86 "CRCW040282R0JNED" 0402 1895,594 r270 bottom
R87 "CRCW040282R0JNED" 0402 1891,785 r270 bottom
R88 "CRCW04021K96FKED" 0402 1078,2483 r90 top
R89 "CRCW0402130RJNED" 0402 1852,676 r270 bottom
R90 "CRCW0402130RJNED" 0402 1933,594 r90 bottom
R91 "CRCW0402130RJNED" 0402 1934,785 r90 bottom
R92 "ERJ-1GE0R00C" 0201M 1433,2506 r270 bottom
R93 "CRCW02011K00FKED" 0201 1330,2505 r270 bottom
R94 "CRCW02011K00FKED" 0201 1281,2475 r90 bottom
R95 "CRCW02011K00FKED" 0201 1330,2577 r270 bottom
R96 "CRCW02011K00FKED" 0201 1281,2404 r90 bottom
Rs1 "CRCW04024K87FKED" 0402 1298,1864 r180 top
S1 "KSR221GLFS" KSR 1654,1333 r0 top
SH-J2 "SPC02SYAN" SPC02SYAN 148,4720 r90 top
SH-J6A "SPC02SYAN" SPC02SYAN 131,6383 r90 top
SH-J6B "SPC02SYAN" SPC02SYAN 139,5866 r90 top
SH-J6C "SPC02SYAN" SPC02SYAN 148,5289 r90 top
SH-J10 "SPC02SYAN" SPC02SYAN 131,6873 r90 top
T1 "ACM9070-701-2PL" ACM9070 2958,3443 r90 top
T2 "HX1188FNLT" Pulse_HX1188FNLT 1138,1228 r270 top
TP1 "TESTPOINT" TP_25MIL-SMT 1188,1816 r90 top
TP2 "TESTPOINT" TP_25MIL-SMT 1249,1815 r90 top
U1 "CDCE925PWR" PW0016A_N 1558,2356 r180 bottom
U2 "DP83822RHBR" RHB0032B 1147,2011 r0 top
U3 "TL1963AQKTTRQ1" KTT0005A_N 3334,1734 r0 bottom
U4 "TL1963AQKTTRQ1" KTT0005A_N 3343,2410 r0 top
U5 "TL1963AQKTTRQ1" KTT0005A_N 3335,1734 r0 top
U6 "TPD4E05U06QDQARQ1" DQA0010A#1 1134,513 r90 bottom
U7 "TPD4E05U06QDQARQ1" DQA0010A#2 1107,1831 r90 top
V+1 "Suggest using a net name here" Keystone1502-2 3543,3105 r90 top
V+2 "Suggest using a net name here" Keystone1502-2 3318,3617 r180 top
Y1 "ABM8AIG-25.000MHZ-12-2Z-T3" Abracon_ABM8AIG 1552,2569 r315 bottom
ZZ1 "This Assembly Note is for PCB labels only" AssemblyNoteLabel 209,7599 r0 top
ZZ2 "These assemblies are ESD sensitive, ESD precautions shall be observed." AssemblyNote 209,7468 r0 top
ZZ3 "These assemblies must be clean and free from flux and all contaminants. Use of no clean flux is not acceptable." AssemblyNote 209,7363 r0 top
ZZ4 "These assemblies must comply with workmanship standards IPC-A-610 Class 2, unless otherwise specified." AssemblyNote 209,7240 r0 top
ZZ5 "Place SH-J2 on pins 1 and 2" AssemblyNote 936,4729 r0 top
ZZ6 "Place Jumper SH-J6A on pins 3 and 4" AssemblyNote 918,6479 r0 top
ZZ7 "Place Jumper SH-J6B on pins 5 and 6" AssemblyNote 936,5910 r0 top
ZZ8 "Place Jumper SH-J6C on pins 11 and 12" AssemblyNote 936,5324 r0 top
ZZ9 "Place Jumper SH-10 on pins 1 and 2" AssemblyNote 909,6925 r0 top

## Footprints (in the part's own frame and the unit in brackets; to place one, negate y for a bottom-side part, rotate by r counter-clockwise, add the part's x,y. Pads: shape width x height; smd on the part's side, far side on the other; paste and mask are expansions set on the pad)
0201 [mm] "Data from Kemet datasheet CC101_COM dated 7/28/11"
  rect 0.46x0.42 smd mask+0.048: 1(-0.33,0) 2(0.33,0)
  body extent -0.31,-0.16 0.31,0.16, height 0.26
0201L [mm] "Data from Kemet datasheet CC101_COM dated 7/28/11"
  rect 0.36x0.32 smd mask+0.048: 1(-0.28,0) 2(0.28,0)
  body extent -0.31,-0.16 0.31,0.16, height 0.26
0201M [mm] "Data from Kemet datasheet CC101_COM dated 7/28/11"
  rect 0.56x0.52 smd mask+0.048: 1(-0.38,0) 2(0.38,0)
  body extent -0.31,-0.16 0.31,0.16, height 0.26
0402 [mm] "0402 from SM-752 data"
  rect 0.8x0.6 smd: 1(-0.6,0) 2(0.6,0)
  silkscreen extent -1.22,-0.52 1.22,0.52, body extent -0.55,-0.3 0.55,0.3, height 0.6
0603 [mm] "0603 from SM-752 data"
  rect 1x0.95 smd: 1(-0.8,0) 2(0.8,0)
  silkscreen extent -1.52,-0.69 1.52,0.69, body extent -0.87,-0.47 0.87,0.47, height 1
0805 [mm] "0805 from SM-752 data"
  rect 1.3x1.5 smd: 1(-0.85,0) 2(0.85,0)
  silkscreen extent -1.72,-0.97 1.72,0.97, body extent -1.1,-0.72 1.1,0.72, height 1.45
0805_HV [mil] "0805 with 30mil clearance between pads"
  rect 50x63 smd: 1(-40,0) 2(40,0)
  silkscreen extent -74,-40 74,40, body extent -43,-29 43,29, height 57
1206 [mm] "1206 from SM-752 data"
  rect 1.3x1.85 smd: 1(-1.45,0) 2(1.45,0)
  silkscreen extent -2.4,-1.21 2.4,1.21, body extent -1.7,-0.9 1.7,0.9, height 1.35
1210_280 [mm] "SMD, 2-Leads, Body 3.6x2.8mm, Height 2.8mm"
  rect 1.1x2.2 smd: 1(-1.65,0) 2(1.65,0)
  silkscreen extent -0.84,-1.4 0.84,1.4, body extent -1.8,-1.4 1.8,1.4, height 2.8
1812_254 [mm] "SMD, 2-Leads, Body 4.8x3.4mm"
  rect 1.6x3.4 smd: 1(-2,0) 2(2,0)
  silkscreen extent -0.8,-1.7 0.8,1.7, body extent -2.4,-1.7 2.4,1.7, height 2.54
Abracon_ABM8AIG [mm] "SMD, 4-Leads, Body 3.2x2.5mm"
  rect 1.1x1.3 smd: 1(-0.95,1.15) 2(-0.95,-1.15) 3(0.95,-1.15) 4(0.95,1.15)
  silkscreen extent -1.8,1.3 -1.27,2.07, body extent -1.3,-1.65 1.3,1.65, height 0.8
ACM9070 [mm] "TDK recommended land pattern 005-02/20090710/e9713_acm"
  rect 2.5x1.5 smd: 1(-4.25,1.75) 2(-4.25,-1.75) 3(4.25,-1.75) 4(4.25,1.75)
  silkscreen extent -5.85,-3.6 5.85,3.6, body extent -4.6,-3.6 4.6,3.6, height 4.5
Amphenol_U77-A1118-200T [mm] "EMI SHIELD, 42.3x16.25 mm, SMT"
  round 1.45 hole 0.95: 1(-7.2,7.125) 2(-2.5,7.125) 3(2.5,7.125) 4(7.1,4.8) 5(7.1,0) 6(7.1,-4.8) 7(2.5,-7.125) 8(-2.5,-7.125) 9(-7.2,-7.125)
  rect 2x2 hole 1.05: 10(-10,1.445) 11(-10,-3.955) 12(-30,-1.455) MH1(-30,7.125) MH2(-20,7.125) MH3(-10,7.125) MH5(5,-7.125) MH6(-5,-7.125) MH7(-15,-7.125) MH8(-25,-7.125)
  rect 2x2 hole 0.85: MH4(0,7.125)
  silkscreen extent -41.18,-7.5 7.8,7.5, body extent -41.18,-7.92 7.8,7.93, height 9.97
AssemblyNote [mil] "Assembly Note"
AssemblyNoteLabel [mil] "Assembly Note for PCB Labels"
DQA0010A#1 [mm] "SON, 10-Leads, Body 1x2.5mm, Pitch 0.5mm, TI Recommended"
  rrect50% 0.565x0.2 smd: 1(-0.417,1) 2(-0.417,0.5) 4(-0.417,-0.5) 5(-0.417,-1) 6(0.417,-1) 7(0.417,-0.5) 9(0.417,0.5) 10(0.417,1)
  rrect28% 0.565x0.36 on Bottom Paste: 3(-0.417,0) 8(0.417,0)
  rrect25% 0.565x0.4 smd paste-0.2: 3(-0.417,0) 8(0.417,0)
  silkscreen extent -0.67,-1.45 0.55,1.45, body extent -0.55,-1.3 0.55,1.3, height 0.56
DQA0010A#2 [mm] "SON, 10-Leads, Body 1x2.5mm, Pitch 0.5mm, TI Recommended"
  rrect50% 0.565x0.2 smd: 1(-0.417,1) 2(-0.417,0.5) 4(-0.417,-0.5) 5(-0.417,-1) 6(0.417,-1) 7(0.417,-0.5) 9(0.417,0.5) 10(0.417,1)
  rrect28% 0.565x0.36 on Top Paste: 3(-0.417,0) 8(0.417,0)
  rrect25% 0.565x0.4 smd paste-0.2: 3(-0.417,0) 8(0.417,0)
  silkscreen extent -0.67,-1.45 0.55,1.45, body extent -0.55,-1.3 0.55,1.3, height 0.56
Emerson_142-0701-851 [mil] "Johnson Components"
  rect 45x200 smd: 1(0,-110)
  rect 95x200 smd: 2(-172.5,-110) 3(172.5,-110)
  rect 95x200 smd far side: 4(172.5,-110) 5(-172.5,-110)
  silkscreen extent -235,-220 235,0, body extent -190,-195 190,387, height 155
FCC_disclaimer [mil]
Fiducial10-20 [mm]
  round 1 smd mask+0.5: 1(0,0)
  Top Layer keep-out circle w1.178: c0,0 r0.5
IFSC-0806AZ-01 [mm] "Vishay-Dale"
  rect 0.85x1.7 smd: 1(-0.725,0) 2(0.725,0)
  body extent -1.1,-0.9 1.1,0.9, height 1
Keystone1502-2 [mm] "Double Turret"
  round 3.5 hole 2.5: 1(0,0)
  silkscreen extent -2.3,-2.3 2.3,2.3, body extent -1.6,-1.6 1.59,1.6, height 5.62
KSR [mm] "C&K Components SPST switch"
  rect 1.5x1.4 smd: 1(-3.25,0) 2(3.25,0)
  silkscreen extent -3.2,-2 3.2,2, body extent -3,-1.9 3,1.9, height 2.65
KTT0005A_N [mm] "D2-PAK, 6-Leads, Body 8.9x10.2mm, Pitch 1.7mm, Lead Span 15.2mm, IPC Medium Density"
  rrect10% 4.15x1 smd: 1(-6.25,3.4) 2(-6.25,1.7) 3(-6.25,0) 4(-6.25,-1.7) 5(-6.25,-3.4)
  rrect1% 8.2x10.75 smd: 6(4.2,0)
  silkscreen extent -6.42,-5.35 -0.3,5.35, body extent -7.63,-5.08 7.63,5.08, height 4.83
Label_1250x250 [mil] "Thermal Transfer Labels"
  round 1 on Mech13: 0(0,0)
  silkscreen extent -625,-125 625,125, body extent -625,-125 625,125, height 1
Molex_0475890001 [mm] "Molex"
  rrect25% 0.4x1.35 smd: 1(-1.3,4.125) 2(-0.65,4.125) 3(0,4.125) 4(0.65,4.125) 5(1.3,4.125)
  oval 1.05x1.3 hole 0.7 slot 0.85 at 90 deg: 6(2.225,4.45) 11(-2.225,4.45)
  oval 0.8x2 hole 0.6 slot 1.3 at 90 deg: 7(4.175,1.45) 10(-4.175,1.45)
  rrect6% 1.8x2 smd: 8(1.15,1.45) 9(-1.15,1.45)
  Top Layer region: 2.6,0.45 2.6,2.45 4.175,2.45 4.175,0.45
  Top Layer region: -4.175,0.45 -4.175,2.45 -2.6,2.45 -2.6,0.45
  silkscreen extent -3.75,2.85 3.75,4.3, body extent -4.32,-1.3 4.33,4.59, height 2.81
Pb-Free_Overlay_Small [mil]
  silkscreen extent -46,-46 46,46
Pulse_HX1188FNLT [mm] "SMD, 16-Leads, Body 12.7x9.09mm, Pitch 1.27mm"
  rect 1.65x0.76 smd: 1(-4.255,4.445) 2(-4.255,3.175) 3(-4.255,1.905) 4(-4.255,0.635) 5(-4.255,-0.635) 6(-4.255,-1.905) 7(-4.255,-3.175) 8(-4.255,-4.445) 9(4.255,-4.445) 10(4.255,-3.175) 11(4.255,-1.905) 12(4.255,-0.635) 13(4.255,0.635) 14(4.255,1.905) 15(4.255,3.175) 16(4.255,4.445)
  silkscreen extent -4.86,-6.42 4.61,6.42, body extent -4.65,-6.42 4.65,6.42, height 6.13
PW0016A_N [mm] "TSOP, 16-Leads, Body 5x4.4mm, Pitch 0.65mm, IPC Medium Density"
  oval 1.4x0.45 smd: 1(-2.95,2.275) 2(-2.95,1.625) 3(-2.95,0.975) 4(-2.95,0.325) 5(-2.95,-0.325) 6(-2.95,-0.975) 7(-2.95,-1.625) 8(-2.95,-2.275) 9(2.95,-2.275) 10(2.95,-1.625) 11(2.95,-0.975) 12(2.95,-0.325) 13(2.95,0.325) 14(2.95,0.975) 15(2.95,1.625) 16(2.95,2.275)
  silkscreen extent -3.5,-2.55 1.85,2.75, body extent -3.21,-2.5 3.21,2.5, height 1
QTLP630C_Green [mm] "SMT, 2-Leads, Body 2x1.25mm"
  rect 1.2x1.2 smd: 1(-1.05,0) 2(1.05,0)
  silkscreen extent -0.15,-0.8 2.15,0.8, body extent -1.1,-0.73 1.1,0.73, height 1.22
RHB0032B [mm] "QFN, 32-Leads, Body 5x5mm, Pitch 0.5mm, Thermal Pad 2.9x2.9mm"
  rrect100% 0.6x0.24 smd: 1(-2.4,1.75) 2(-2.4,1.25) 3(-2.4,0.75) 4(-2.4,0.25) 5(-2.4,-0.25) 6(-2.4,-0.75) 7(-2.4,-1.25) 8(-2.4,-1.75) 17(2.4,-1.75) 18(2.4,-1.25) 19(2.4,-0.75) 20(2.4,-0.25) 21(2.4,0.25) 22(2.4,0.75) 23(2.4,1.25) 24(2.4,1.75)
  rrect100% 0.24x0.6 smd: 9(-1.75,-2.4) 10(-1.25,-2.4) 11(-0.75,-2.4) 12(-0.25,-2.4) 13(0.25,-2.4) 14(0.75,-2.4) 15(1.25,-2.4) 16(1.75,-2.4) 25(1.75,2.4) 26(1.25,2.4) 27(0.75,2.4) 28(0.25,2.4) 29(-0.25,2.4) 30(-0.75,2.4) 31(-1.25,2.4) 32(-1.75,2.4)
  rrect3% 2.9x2.9 smd paste-1.725: 33(0,0)
  silkscreen extent -2.72,-2.73 2.72,2.72, body extent -2.57,-2.58 2.58,2.57, height 1.01
Samtec_TSW-103-07-T-S [mm] "Header, 2.54 mm, 3x1, TH"
  rect 1.55x1.55 hole 1.02: 1(-2.54,0)
  round 1.55 hole 1.02: 2(0,0) 3(2.54,0)
  silkscreen extent -3.81,-1.75 3.81,1.27, body extent -3.81,-1.27 3.81,1.27, height 8.39
SMA [mm] "Molded Diode, 2-Leads, Body 4.3x2.6mm, IPC Medium Density, based on OnSemi component dimensions and land pattern"
  rect 2x2 smd: 1(-2,0) 2(2,0)
  silkscreen extent -3.66,-1.57 2.79,1.57, body extent -2.6,-1.3 2.6,1.3, height 2.42
SPC02SYAN [mil] "SULLINS"
  round 1 on Mech3: 0(0,0)
  body extent -98,-47 99,47, height 366
TE_1367073-1 [mm] "SMD, 20-Leads, Body 11.2x7.4mm, Pitch 0.8mm"
  rect 2x0.5 smd: 1(-4.1,3.4) 2(-4.1,2.6) 3(-4.1,1.8) 4(-4.1,1) 5(-4.1,0.2) 6(-4.1,-0.6) 7(-4.1,-1.4) 8(-4.1,-2.2) 9(-4.1,-3) 10(-4.1,-3.8) 11(4.1,-3.4) 12(4.1,-2.6) 13(4.1,-1.8) 14(4.1,-1) 15(4.1,-0.2) 16(4.1,0.6) 17(4.1,1.4) 18(4.1,2.2) 19(4.1,3) 20(4.1,3.8)
  round 0 hole 1.55 unplated: MH1(0,4.8) MH2(0,-4.8)
  Top Layer keep-out region: -2.88,-3.85 2.88,-3.85 2.88,-3.99 3.94,-3.99 3.94,-5.75 -4.34,-5.75 -4.34,-4.39 -2.88,-4.39
  Top Layer keep-out region: -4.34,5.75 3.94,5.75 3.94,4.39 2.88,4.39 2.88,3.85 -2.88,3.85 -2.88,3.99 -4.34,3.99
  silkscreen extent -5.1,-5.7 4.8,5.7, body extent -4.5,-5.5 4.5,5.5, height 5.2
TEC_1-406541-1 [mm] "TE Connectivity"
  round 1.4 hole 0.89: 1(3.56,-0.18) 2(2.54,1.6) 3(1.52,-0.18) 4(0.5,1.6) 5(-0.52,-0.18) 6(-1.54,1.6) 7(-2.56,-0.18) 8(-3.58,1.6)
  round 2.1 hole 1.57: 9(8.12,0.71) 10(-8.14,0.71)
  round 3.759 hole 3.251: 11(6.34,-2.72) 12(-6.36,-2.72)
  silkscreen extent -9.69,-8 9.69,8.06, body extent -9.33,-8 9.31,7.75, height 14.8
TESTPOINT [mil]
  round 315 hole 126: 1(0,0)
TI_Horizontal_Overlay_Medium [mil]
  silkscreen extent -750,-94 750,94
TNPW0603 [mm] "Vishay"
  rect 0.5x0.9 smd: 1(-0.75,0) 2(0.75,0)
  silkscreen extent -0.2,-0.6 0.2,0.6, body extent -0.85,-0.47 0.85,0.47, height 0.55
TP_25MIL-SMT [mil]
  round 25 smd mask-2.5: 1(0,0)
TSW-103-07-G-S [mm] "Samtec 100mil, 1x3, 230 mil above insulator"
  rect 1.65x1.65 hole 1.016: 1(-2.54,0)
  round 1.65 hole 1.016: 2(0,0) 3(2.54,0)
  silkscreen extent -3.81,-1.27 3.81,1.65, body extent -3.81,-1.27 3.81,1.27, height 8.38
TSW-106-07-G-D [mm] "Samtec 100mil, 2x6, 230 mil above insulator"
  rrect6% 1.65x1.65 hole 1.016: 1(-6.35,-1.27)
  round 1.65 hole 1.016: 2(-6.35,1.27) 3(-3.81,-1.27) 4(-3.81,1.27) 5(-1.27,-1.27) 6(-1.27,1.27) 7(1.27,-1.27) 8(1.27,1.27) 9(3.81,-1.27) 10(3.81,1.27) 11(6.35,-1.27) 12(6.35,1.27)
  silkscreen extent -8.64,-2.54 7.62,2.54, body extent -7.62,-2.54 7.62,2.54, height 8.38
TSW-107-07-G-D [mm] "Samtec 100mil, 2x7, 230 mil above insulator"
  rrect6% 1.65x1.65 hole 1.016: 1(-7.62,-1.27)
  round 1.65 hole 1.016: 2(-7.62,1.27) 3(-5.08,-1.27) 4(-5.08,1.27) 5(-2.54,-1.27) 6(-2.54,1.27) 7(0,-1.27) 8(0,1.27) 9(2.54,-1.27) 10(2.54,1.27) 11(5.08,-1.27) 12(5.08,1.27) 13(7.62,-1.27) 14(7.62,1.27)
  silkscreen extent -9.91,-2.54 8.89,2.54, body extent -8.89,-2.54 8.89,2.54, height 8.38
TSW-113-07-G-D [mm] "Samtec 100mil, 2x13, 230 mil above insulator"
  rrect6% 1.65x1.65 hole 1.016: 1(-15.24,-1.27)
  round 1.65 hole 1.016: 2(-15.24,1.27) 3(-12.7,-1.27) 4(-12.7,1.27) 5(-10.16,-1.27) 6(-10.16,1.27) 7(-7.62,-1.27) 8(-7.62,1.27) 9(-5.08,-1.27) 10(-5.08,1.27) 11(-2.54,-1.27) 12(-2.54,1.27) 13(0,-1.27) 14(0,1.27) 15(2.54,-1.27) 16(2.54,1.27) 17(5.08,-1.27) 18(5.08,1.27) 19(7.62,-1.27) 20(7.62,1.27) 21(10.16,-1.27) 22(10.16,1.27) 23(12.7,-1.27) 24(12.7,1.27) 25(15.24,-1.27) 26(15.24,1.27)
  silkscreen extent -17.53,-2.54 16.51,2.54, body extent -16.51,-2.54 16.51,2.54, height 8.38

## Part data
C4 C5: "CAP, CERM, 12 pF, 25 V, +/- 5%, C0G/NP0, AEC-Q200 Grade 1, 0402"
C6 C7: "CAP, CERM, 2.2 µF, 16 V, +/- 10%, X5R, 0402"
C8 C15 C22 C43 C45 C54 C56 C58 C61 C63 C65: "CAP, CERM, 0.1 µF, 16 V, +/- 10%, X7R, 0402"
C9 C10 C11 C16 C23 C31 C53 C57: "CAP, CERM, 0.01 µF, 50 V, +/- 10%, X7R, AEC-Q200 Grade 1, 0402"
C12 C19 C29 C37 C39 C40: "CAP, CERM, 22 µF, 16 V, +/- 20%, X7R, AEC-Q200 Grade 1, 1210"
C13 C20 C26 C27 C30 C34 C35 C36 C38 C59: "CAP, CERM, 10 µF, 25 V, +/- 20%, X7R, AEC-Q200 Grade 1, 1210"
C14 C21 C42 C44 C55 C60 C62 C64: "CAP, CERM, 1 µF, 10 V, +/- 10%, X7S, 0402"
C17 C24 C32: "CAP, CERM, 1000 pF, 50 V, +/- 5%, C0G/NP0, AEC-Q200 Grade 1, 0402"
C18 C25 C33: "CAP, CERM, 100 pF, 50 V, +/- 5%, C0G/NP0, AEC-Q200 Grade 1, 0402"
C28 C51 C52 C66 C67: "CAP, CERM, 4700 pF, 2000 V, +/- 10%, X7R, 1812"
C41 C46: "CAP, CERM, 0.01 µF, 250 V, +/- 5%, C0G/NP0, AEC-Q200 Grade 1, 0805"
C47 C48 C49 C50: "CAP, CERM, 0.1 µF, 25 V, +/- 10%, X8R, AEC-Q200 Grade 0, 0603"
C68 C69: "CAP, CERM, 4700 pF, 100 V, +/- 10%, X7R, 0805"
D1 D2 D4 D5 D6 D7: "LED, Green, SMD"
D3: "Diode, Schottky, 60 V, 1 A, AEC-Q101, SMA"
FID1 FID2 FID3: "Fiducial mark.  There is nothing to buy or mount."
GND1 GND2 J7 J8 J9 V+1 V+2: library part 1502-2, "Terminal, Turret, TH, Double"
H1: "SFP Single Cage"
J1 J4: library part 142-0701-851, "Connector, End launch SMA, 50 ohm, SMT"
J2: "Header, 2.54 mm, 3x1, Tin, TH"
J5: "Connector, Receptacle, Micro-USB Type AB, R/A, Bottom Mount SMT"
J6: "Header, 100mil, 6x2, Gold, TH"
J10 J11: "Header, 100mil, 3x1, Gold, TH"
J12: "RJ-45, No LED, tab up, R/A, TH"
J13: "Header, 100mil, 7x2, Gold, TH"
J14: "Header, 100mil, 13x2, Gold, TH"
J15: "Receptacle, 0.8mm, 10x2, Gold, R/A, SMT"
L2: "Ferrite Bead, 120 ohm @ 100 MHz, 0.2 A, 0805"
L3 L4: "Inductor, Shielded, Ferrite, 1 µH, 1.6 A, 0.115 ohm, SMD"
LBL1: library part THT-13-457-10, "Thermal Transfer Printable Labels, 1.250\" W x 0.250\" H - 10,000 per roll"
Logo1: library part TI_Logo, "Texas Instrument Corporate Signature"
Logo2: library part Pb-Free
Logo3: library part FCC_disclaimer, "FCC_disclaimer"
M1 M2 M3 M4 TP1 TP2: "TEST POINT.  No entry in BOM."
R1 R2: "RES, 1.00 k, 1%, 0.063 W, 0402"
R3: "RES, 18, 5%, 0.063 W, 0402"
R4 R74: "RES, 0, 5%, 0.063 W, 0402"
R5 R6 R8 R9 R10: "RES, 2.21 k, 0.1%, 0.1 W, AEC-Q200 Grade 0, 0603"
R7 R28 R29 R30 R31 R36 R41 R42 R44 R46 R47 R49 R50 R51 R52 R54 R56 R57 R58 R59 R61 R62 R63 R64 R65 R67 R68 R69 R70 R92: "RES, 0, 5%, 0.05 W, 0201"
R11 R43 R83: "RES, 1.00 M, 1%, 0.25 W, 1206"
R12 R13 R17 R20 R23 R25: "RES, 470, 5%, 0.063 W, 0402"
R14: "RES, 1.20 k, 0.1%, 0.1 W, 0603"
R15 R21 R27: "RES, 2.40 k, 0.1%, 0.1 W, AEC-Q200 Grade 0, 0603"
R16 R18 R22 R24 R48 R72 R76 R78 R82: "RES, 2.49 k, 1%, 0.063 W, 0402"
R19 R26: "RES, 4.22 k, 1%, 0.1 W, 0603"
R32 R33 R34 R35: "RES, 75, 5%, 0.125 W, 0805"
R37 R38 R39 R40: "RES, 49.9, 1%, 0.063 W, 0402"
R45 R71 R75 R77 R80: "RES, 10.0 k, 1%, 0.063 W, 0402"
R53 R60: "RES, 13.0 k, 1%, 0.063 W, 0402"
R55 R66 R88: "RES, 1.96 k, 1%, 0.063 W, 0402"
R73: "RES, 10 k, 5%, 0.1 W, 0603"
R79 R85 R86 R87: "RES, 82, 5%, 0.063 W, 0402"
R81 R89 R90 R91: "RES, 130, 5%, 0.063 W, 0402"
R84: "RES, 6.2 k, 5%, 0.063 W, 0402"
R93 R94 R95 R96: "RES, 1.00 k, 1%, 0.05 W, 0201"
Rs1: "RES, 4.87 k, 1%, 0.063 W, 0402"
S1: "Switch, Normally open, 2.3N force, 200k operations, SMD"
SH-J2 SH-J6A SH-J6B SH-J6C SH-J10: "Shunt, 100mil, Flash Gold, Black"
T1: "Common Mode Filter for Power Line"
T2: "Transformer, 350 uH, SMT"
U1: "PROGRAMMABLE 2-PLL VCXO CLOCK SYNTHESIZER WITH 1.8-V, 2.5-V and 3.3-V LVCMOS OUTPUTS, PW0016A"
U2: "10/100 Ethernet PHY, RHB0032B"
U3 U4 U5: "Single Output Fast Transient Response LDO, 1.5 A, Adjustable 1.21 to 20 V Output, 2.1 to 20 V Input, 5-pin DDPAK (KTT), -40 to 125 degC, Green (RoHS & no Sb/Br)"
U6 U7: "1, 4, 6 CHANNEL PROTECTION SOLUTION FOR SUPER-SPEED (UP TO 6 GBPS) INTERFACE, DQA0010A"
Y1: "Crystal, 25MHz, 12pF, SMD"
ZZ1: library part AssemblyNoteLabel
ZZ2 ZZ3 ZZ4: library part AssemblyNote
ZZ5 ZZ6 ZZ7 ZZ8 ZZ9: library part "Assembly Note"

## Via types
v1: diameter 22, hole 11, Top Layer to Bottom Layer, 107 vias
v2: diameter 12, hole 6, Top Layer to Bottom Layer, 74 vias
v3: diameter 20, hole 10, Top Layer to Bottom Layer, 10 vias
v4: diameter 19.68, hole 7.87, Top Layer to Bottom Layer, 5 vias
v5: diameter 25, hole 12, Top Layer to Bottom Layer, 1 vias

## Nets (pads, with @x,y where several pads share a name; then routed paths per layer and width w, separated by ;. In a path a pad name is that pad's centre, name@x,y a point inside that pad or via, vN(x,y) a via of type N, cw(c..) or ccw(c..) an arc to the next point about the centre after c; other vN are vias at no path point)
3V3: C40.1 C42.1 C43.1 C44.1 C45.1 C55.1 C56.1 C60.1 C61.1 C62.1 C63.1 C64.1 C65.1 J6.6 J6.8 L3.1 L4.1 R37.2 R38.2 R39.2 R40.2 R79.2 R85.2 R86.2 R87.2 T2.2 T2.7 | length 1991.4
  Top Layer w15: v2(1013,1353.38) T2.7@1013,1400.44 ; v2(1263,1353.38) T2.2@1263,1400.44 ; v2@1811,733 C61.1@1811,699.62 C60.1@1852,699.62 ; v2(1811,920) 1811,888.62 C55.1@1852,888.62 ; v2(1891,733) C65.1@1891,761.38 C64.1@1926,761.38 ; v2(1893,533) cw(c1895.41,535.41) 1892,535.41 1892,570.38 C62.1@1926,570.38 ; v2@2260.54,843.54 2307,843.54 L4.1@2390,843.54
  Signal Layer 2 w15: v2(1811,920) 1873,982 2121,982 v2(2260,843)
  Bottom Layer w15: R40.2@1032,1557.62 R39.2@994,1557.62 912.62,1557.62 871,1516 871,1390 907.62,1353.38 966,1353.38 v2(1013,1353.38) 1059,1353.38 1216,1353.38 v2(1263,1353.38) C44.1@1309,1353.38 ; R37.2@1243,1557.62 R38.2@1282,1557.62 v2@1308.62,1557.62 ; R85.2@1811,699.62 v2@1811,733 ; R79.2@1811,888.62 v2(1811,920) ; v2(1891,733) R87.2@1891,761.38 ; R86.2@1892,570.38 1892,535.41 ccw(c1895.41,535.41) v2(1893,533)
  other v2: 1812,734 968,1558 1309,1558
3V3_EXT: J6.7 J9.1 | length 223.2
  Top Layer w30: J6.7@2432,2239 2535,2239 J9.1@2620,2154
3V3A: C7.1 C8.1 C10.1 C11.1 L2.2 U1.6 U1.9 | length 664.2
  Bottom Layer w20: C10.1@1374.19,2266.43 U1.9@1441.86,2266.43 1566.43,2266.43 1617.61,2317.61 U1.6@1674.14,2317.61 C11.1@1769.76,2317.61 ; C11.1@1772.24,2317.38 C8.1@1886,2317.38 ; C8.1@1888.38,2315 L2.2@2022,2315
5V_20V: C29.1 C30.1 C31.1 C32.1 C33.1 C34.1 C36.1 C38.1 D3.1 U3.1 U3.2 U4.1 U4.2 U5.1 U5.2 V+1.1 | length 1847.1
  Top Layer w40: C38.1@2813.1,1867.86 U5.1@3087.94,1867.86 ; U5.2@3087.94,1800.93 U5.1@3087.94,1867.86 ; U4.2@3096.94,2476.93 3213.07,2476.93 3246,2444 v1(3246,1911) 3203,1868 3087.8,1868 U5.1@3087.94,1867.86
  Bottom Layer w30: C34.1@2894.18,1600.14 U3.1@3087.94,1600.14 U3.2@3087.94,1667.07 3196.07,1667.07 3246,1717 v1(3246,1911)
+1V8: C9.1 C35.1 R1.2 R14.2 R93.2 R94.2 U1.3 U3.4 | length 3070.8
  Signal Layer 2 w20: v2(1355,2489) 1450,2394 v2(1629,2394)
  Bottom Layer w20: R94.2@1281.08,2490.04 1330,2490.04 v2@1353.96,2490.04 ; v2@1629.39,2394.39 U1.3@1674.14,2394.39 C9.1@1768.99,2394.39 ; C9.1@1769.38,2394 1769.38,2458.38 1903,2592 2106,2592 2198.62,2684.62 R1.2@2198.62,2896
  Bottom Layer w30: R1.2@2198.62,2896 2506,2896 2912.5,2489.5 R14.2@2912.5,1984 C35.1@2912.5,1804.54 ; C35.1@2908.89,1800.93 U3.4@3087.94,1800.93
AVD: C19.1 C20.1 C21.1 C22.1 C23.1 C24.1 C25.1 D1.1 J6.10 J6.12 U2.14 | length 1965.3
  Top Layer w10: v2@1176.53,1890.47 U2.14@1176.53,1916.51
  Top Layer w40: D1.1@2186.34,2139 2186.34,2281.34 2244,2339 J6.10@2332,2339 J6.12@2332,2439
  Signal Layer 4 w40: v1@1619,1862 1619,1908 1649,1938 1931,1938 2087,2094 2087,2298 2128,2339 J6.10@2332,2339
  Bottom Layer w30: v2(1177,1890) C25.1@1177,1861.62 C24.1@1212,1861.62 C23.1@1249,1861.62 v1(1619,1861.62)
AVD_EXT: J6.9 J8.1 | length 406.4
  Top Layer w30: J6.9@2432,2339 2540,2447 2540,2555 J8.1@2437,2658
AVD_INT: C37.1 J6.5 J6.11 R19.2 U4.4 | length 1128.2
  Top Layer w20: v3@2600.96,2339.04 C37.1@2672,2339.04 2672,2299 2698,2273 R19.2@2898.5,2273 2898.5,2327.5 2914.07,2343.07 U4.4@3096.94,2343.07 U4.4@3092.91,2339.04
  Signal Layer 4 w20: J6.5@2432,2139 2600,2307 v3(2600,2340) 2600,2400 2561,2439 J6.11@2432,2439
COL: R61.2 U2.29 | length 31.3
  Top Layer w10: U2.29@1137.16,2105.49 R61.2@1137.16,2136.82
CRS: R63.2 U2.27 | length 31.6
  Top Layer w10: R63.2@1176,2136.98 cw(c1174.73,2135.7) 1176.53,2135.7 U2.27@1176.53,2105.49
EARTH: C41.2 C46.2 C51.2 C52.2 J12.9 J12.10 J12.11 J12.12 M1.1 R43.1 U6.3@1134,496.56 U6.8@1134,529.44 | length 101.5
  Bottom Layer w15: U6.3@1134,496.27 U6.8@1134,529.73
  Bottom Layer w20: v5(1178,759) C46.2@1178,827
  other v2: 1134,514
EXT_CLK: J1.1 R4.1 | length 2208.7
  Top Layer w10: J1.1@111,3294 v2@238,3294 ; v2(1281,2165) 1286,2160 R4.1@1286,2113.62
  Signal Layer 4 w4.5: v2(239,3295) 1016.58,3295 cw(c1016.58,3195) 1087.29,3265.71 1233.71,3119.29 cw(c1163,3048.58) 1263,3048.58 1263,2181 1275,2169 ; v2@1279,2165 v2(1281,2165)
FX_RD_N: J15.12 R36.2 R86.1 R90.2 | length 1012.3
  Signal Layer 4 w4.5: v2(1123,661) cw(c1130.85,653.15) 1130.85,664.25 1152.74,664.25 cw(c1152.74,649.74) 1163,660 ccw(c1243.88,740.88) 1243.88,626.5 1735.53,626.5 cw(c1735.53,611.69) v2(1746,622.16)
  Bottom Layer w11: R36.2@1101.02,661 v2(1123,661) ; v2(1746,622.16) 2053.46,622.16 ccw(c2058.89,627.59) 2058.89,619.91 J15.12@2100.58,619.91
FX_RD_P: J15.13 R41.2 R85.1 R89.2 | length 1011.7
  Signal Layer 4 w4.5: v2(1123,688) ccw(c1130.85,695.85) 1130.85,684.75 1152.74,684.75 cw(c1152.74,649.74) 1177.5,674.5 ccw(c1243.88,740.88) 1243.88,647 1740.78,647 ccw(c1740.78,654.38) v2(1746,649.16)
  Bottom Layer w11: R41.2@1101.02,688 v2(1123,688) ; v2(1746,649.16) 2053.46,649.16 cw(c2058.89,643.74) 2058.89,651.41 J15.13@2100.58,651.41
FX_TD_N: J15.19 R42.2 R79.1 R81.2 | length 1023.7
  Signal Layer 4 w4.5: v2(1317,886) ccw(c1324.85,893.85) 1324.85,882.75 1351.33,882.75 cw(c1351.33,844.33) 1378.5,871.5 1430.13,819.86 cw(c1400.27,790) 1442.5,790 ccw(c1484.75,790) 1454.87,760.13 1457,758 ccw(c1481.14,782.14) 1481.14,748 1527.51,748 ccw(c1527.51,768.49) 1542,754 1587.21,799.21 cw(c1672.41,714) 1672.41,834.5 1735.21,834.5 ccw(c1735.21,846.92) v2(1744,838.14)
  Bottom Layer w11: R42.2@1250,786.02 1250,798.61 1249.5,799.11 1249.5,825.14 cw(c1291.86,825.14) 1261.9,855.08 1275.72,868.9 cw(c1317,827.62) v2(1317,886) ; v2(1744,838.14) 2053.46,838.14 2055.71,840.39 J15.19@2100.58,840.39
FX_TD_P: J15.18 R44.2 R87.1 R91.2 | length 981
  Signal Layer 4 w4.5: v2(1317,859) cw(c1324.85,851.15) 1324.85,862.25 1351.33,862.25 cw(c1351.33,844.33) 1364,857 1415.64,805.36 cw(c1400.27,790) 1422,790 ccw(c1484.75,790) 1440.38,745.63 1442.5,743.5 ccw(c1481.14,782.14) 1481.14,727.5 1527.51,727.5 ccw(c1527.51,768.49) 1556.5,739.5 1601.7,784.71 cw(c1672.41,714) 1672.41,814 1737.09,814 cw(c1737.09,804.23) v2(1744,811.14)
  Bottom Layer w11: R44.2@1276,786.02 1276,798.61 1276.5,799.11 1276.5,825.14 cw(c1291.86,825.14) 1281,836 1294.81,849.81 cw(c1317,827.62) v2(1317,859) ; v2(1744,811.14) 2053.46,811.14 2055.71,808.89 J15.18@2100.58,808.89
GND: C4.2 C5.2 C6.2 C7.2 C8.2 C9.2 C10.2 C11.2 C12.2 C13.2 C14.2 C15.2 C16.2 C17.2 C18.2 C19.2 C20.2 C21.2 C22.2 C23.2 C24.2 C25.2 C26.2 C27.2 C28.1 C29.2 C30.2 C31.2 C32.2 C33.2 C34.2 C35.2 C36.2 C37.2 C38.2 C39.2 C40.2 C42.2 C43.2 C44.2 C45.2 C51.1 C52.1 C53.2 C54.2 C55.2 C56.2 C57.2 C58.2 C59.2 C60.2 C61.2 C62.2 C63.2 C64.2 C65.2 C66.1 C67.1 C68.2 C69.2 D5.2 D7.2 GND1.1 J1.2 J1.3 J1.4 J1.5 J4.2 J4.3 J4.4 J4.5 J13.2 J13.4 J13.6 J13.8 J13.10 J13.12 J13.14 J14.2 J14.4 J14.6 J14.8 J14.10 J14.12 J14.14 J14.16 J14.18 J14.20 J14.22 J14.24 J14.26 J15.1 J15.3 J15.9 J15.10 J15.11 J15.14 J15.17 J15.20 R2.1 R9.1 R10.1 R11.2 R12.1 R13.1 R15.1 R18.1 R21.1 R24.1 R27.1 R43.2 R48.1 R55.1 R66.1 R72.1 R76.1 R78.1 R81.1 R82.1 R83.2 R88.1 R89.1 R90.1 R91.1 R95.1 R96.1 Rs1.1 T1.1 U1.5 U1.12 U2.33 U3.3 U3.6 U4.3 U4.6 U5.3 U5.6 U7.3@1107,1814.56 U7.8@1107,1847.44 Y1.2 Y1.4 | length 830.9
  Top Layer w15: U7.3@1107,1814.27 U7.8@1107,1847.73
  Top Layer w30: R88.1@1078,2459.38 1078,2398 1092.38,2383.62 R66.1@1118,2383.62 ; v3(2040,682) 2053,669 C57.2@2119.38,669 C58.2@2119.38,617 ; C54.2@2166,833.62 C53.2@2219,833.62 ; C59.2@2388,541.04 v3@2464.96,541.04
  Bottom Layer w30: C42.2@966,1400.62 1059,1400.62 1216,1400.62 C44.2@1309,1400.62 ; 1136,1402.62 C40.2@1136,1482.96
  other v1: 2073,102 1828,103 2822,105 3031,105 1827,314 2073,314 2820,318 3032,318 1675,582 1576,585 1419,586 1509,586 1463,587 1508,695 1575,707 1439,711 1676,772 1507,799 1575,839 1463,840 1675,876 1421,880 142,940 668,940 417,942 144,1185 415,1188 668,1193 2145,1342 3459,1343 2375,1344 3056,1347 144,1434 415,1434 668,1436 2375,1620 2147,1622 445,1695 551,1695 365,1697 370,1795 446,1796 362,1895 445,1898 768,1955 651,1956 551,1959 362,1993 446,2064 364,2113 513,2116 1379,2161 578,2169 363,2201 820,2213 895,2294 730,2295 818,2363 651,2365 898,2408 1878,2422 563,2446 729,2446 822,2486 499,2527 652,2528 937,2548 1214,2563 421,2609 2648,2610 2196,2611 566,2612 855,2625 987,2627 357,2693 497,2693 938,2713 1053,2713 752,2724 848,2727 421,2770 3649,2782 3306,2783 2255,2813 443,2865 2069,3191 3303,3191 1661,3194 3608,3194 1246,3196 849,3198 449,3204 1247,3510 848,3512 1664,3512 2068,3513 449,3514 846,3898 1663,3898 2068,3899 1247,3900
  other v2: 1107,1832 1333,2394
  other v3: 2466,540 2192,833.62 1080,2426
  other v4: 1147,1964.74 1100.74,2011 1147,2011 1193.26,2011 1147,2057.26
INT_PWDN_N: C26.1 R6.1 R9.2 R46.2 U2.8 | length 402
  Top Layer w10: R6.1@806,1768.53 C26.1@945.57,1768.53 ; C26.1@946,1768.96 946,1828 975.02,1857.02 R46.2@975.02,1942 ; R46.2@975.13,1942.1 U2.8@1052.51,1942.1
LED_0: J10.2 U2.17 | length 692.9
  Top Layer w10: U2.17@1241.49,1942.1 1241.49,1920.51 1258,1904 1773,1904 J10.2@1867,1810
LED_GPIO: J11.2 R67.2 R74.1 U2.24 | length 3896.3
  Top Layer w10: U2.24@1241.49,2079.9 1241.49,2099.49 ccw(c1240.25,2100.72) 1242,2100.72 R67.2@1242,2136.98 ; R74.1@2169,520.38 2201.62,520.38 2285,437 v3(2285,329)
  Signal Layer 1 w10: v2(1242,2100) 1767,2100 J11.2@1867,2200 1867,2001 2090,1778 2447,1778 2814,1411 2814,478 2665,329 v3(2285,329)
LOS: J15.8 R73.1 R74.2 | length 299.6
  Top Layer w10: R74.2@2169,567.62 2217.62,567.62 2227,577 R73.1@2227,606.5 v3@2269.5,606.5
  Bottom Layer w7: v3(2270,606) 2322,606 2351.66,635.66 J15.8@2423.41,635.66
MDC: R68.2 U2.20 | length 54.3
  Top Layer w10: U2.20@1241.49,2001.16 R68.2@1295.82,2001.16
MDIO: R5.1 R69.2 U2.19 | length 156.5
  Top Layer w10: U2.19@1242.02,1982 R69.2@1348,1982 ; R69.2@1348,1980.98 R5.1@1398.5,1980.98
NetC4_1: C4.1 U1.1 Y1.3 | length 184
  Bottom Layer w10: Y1.3@1609.77,2575.26 1627.03,2558 C4.1@1674.38,2558 U1.1@1674.38,2445.8
NetC5_1: C5.1 R92.1 Y1.1 | length 92.2
  Bottom Layer w10: R92.1@1433,2520.96 C5.1@1433,2553.62 ; C5.1@1433,2561 Y1.1@1492.5,2561
NetC41_1: C41.1 R32.1 R33.1 | length 228.5
  Bottom Layer w40: R33.1@892,128 R32.1@1030,128 C41.1@1120.46,128
NetC46_1: C46.1 R34.1 R35.1 | length 154.4
  Bottom Layer w30: C46.1@1098,827 1098,900 1178,900 R35.1@1179,901
NetC68_1: C68.1 M3.1 | length 249
  Top Layer w40: M3.1@205,3812 C68.1@454,3812
NetC69_1: C69.1 M4.1 | length 225
  Top Layer w40: C69.1@3526,3589 M4.1@3526,3814
NetD1_2: D1.2 R12.2 | length 56
  Top Layer w7: D1.2@2103,2139 D1.2@2103.66,2138.34
  Top Layer w20: R12.2@2103.66,2083.96 2103.66,2138.34 D1.2@2103.66,2139
NetD2_2: D2.2 R13.2 | length 58.5
  Top Layer w20: R13.2@2103.97,1879.65 D2.2@2103.97,1938.15
NetD3_2: D3.2 T1.2 | length 145
  Top Layer w30: T1.2@3045.96,3294.74 D3.2@3191,3294.74
NetD4_1: D4.1 R17.1 | length 67
  Top Layer w20: R17.1@1768,1570.62 D4.1@1768,1637.66
NetD4_2: D4.2 J10.1 R16.2 | length 284.4
  Top Layer w10: D4.2@1767,1721.34 1805.66,1721.34 1821,1706 R16.2@1821,1570.62
  Top Layer w20: D4.2@1767,1721.34 J10.1@1767,1810
NetD5_1: D5.1 R20.2 | length 75
  Top Layer w10: D5.1@1969,1589.34 R20.2@1969,1664.38
NetD6_1: D6.1 R23.1 | length 57
  Top Layer w20: D6.1@1765,2373.34 R23.1@1765,2430.38
NetD6_2: D6.2 J11.1 R22.2 | length 272.3
  Top Layer w10: D6.2@1767,2288.66 1802.66,2288.66 1813,2299 R22.2@1813,2432.38
  Top Layer w20: J11.1@1767,2200 D6.2@1767,2288.66
NetD7_1: D7.1 R25.2 | length 59
  Top Layer w20: R25.2@1967,2331.62 D7.1@1967,2390.66
NetGND2_1: GND2.1 J5.5 T1.4 | length 529
  Top Layer w15: T1.4@2905.82,3627.04 J5.5@2905.82,3870.6
  Top Layer w40: GND2.1@2603.68,3610.32 T1.4@2889.1,3610.32
NetJ2_1: J2.1 R2.2 | length 115.4
  Top Layer w10: J2.1@2034,2695 R2.2@2149.38,2695
NetJ2_2: J2.2 U1.2 | length 546.2
  Bottom Layer w20: U1.2@1674.14,2419.98 1711.98,2419.98 1737,2445 1737,2498 J2.2@2034,2795
NetJ2_3: J2.3 R1.1 | length 116.4
  Bottom Layer w20: J2.3@2035,2896 R1.1@2151.38,2896
NetJ4_1: J4.1 R7.1 | length 1207.5
  Top Layer w10: J4.1@120.66,2763 cw(c120.66,2776.66) 111,2767 233.59,2767 ccw(c233.59,2770.41) v2(236,2768) ; v2(975,2081) R7.1@993.01,2081
  Signal Layer 1 w4.5: v2(236,2768) 309.58,2768 cw(c309.58,2668) 380.29,2738.71 957,2162 cw(c913.54,2118.54) 975,2118.54 v2(975,2081)
NetJ5_1: J5.1 T1.3 V+2.1 | length 526
  Top Layer w15: T1.3@3008.18,3629.04 J5.1@3008.18,3870.6
  Top Layer w30: T1.3@3033.57,3617 V+2.1@3318,3617
NetJ10_3: J10.3 R18.2 R20.1 | length 151.6
  Top Layer w10: J10.3@1967,1810 1967,1713.62 R20.1@1969,1711.62 1970,1710.62 R18.2@2021,1710.62
NetJ11_3: J11.3 R24.2 R25.1 | length 140.4
  Top Layer w20: J11.3@1967,2200 R25.1@1967,2284.38 R24.2@2023,2284.38
NetJ12_4: J12.4 J12.5 R32.2 | length 203.5
  Bottom Layer w20: J12.4@1006.68,373.99 1006.68,337.51 973.09,303.91 1030,247 R32.2@1030,208
NetJ12_7: J12.7 J12.8 R33.2 | length 176.8
  Bottom Layer w20: J12.8@846.06,373.99 846.06,344.07 J12.7@886.21,303.91 ; R33.2@892,208 J12.7@892,298.13
NetJ13_1: J13.1 R46.1 | length 793.5
  Top Layer w7: v2(935,1941) R46.1@952.98,1941
  Signal Layer 1 w7: J13.1@277,1647 599.58,1647 ccw(c599.58,1747) 670.29,1676.29 v2(935,1941)
NetJ13_3: J13.3 R47.1 | length 801.1
  Top Layer w7: v2(975,1961) 993.98,1961 R47.1@994.98,1962
  Signal Layer 1 w4.5: J13.3@277,1747 633.58,1747 ccw(c633.58,1847) 704.29,1776.29 876.5,1948.5 cw(c904.98,1922.38) 903.73,1961 v2(975,1961)
NetJ13_5: J13.5 R49.1 | length 803.1
  Top Layer w7: v2(931,1982) R49.1@952.98,1982
  Signal Layer 1 w4.5: J13.5@277,1847 384.13,1847 ccw(c384.13,1911.87) 430,1866 cw(c444.49,1851.51) 444.49,1872 490.81,1872 cw(c490.81,1849.81) 506.5,1865.5 592,1780 ccw(c613.73,1801.73) 613.73,1771 637,1771 ccw(c637,1848.25) 691.63,1793.63 858,1960 cw(c911.11,1906.89) 911.11,1982 v2(931,1982)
